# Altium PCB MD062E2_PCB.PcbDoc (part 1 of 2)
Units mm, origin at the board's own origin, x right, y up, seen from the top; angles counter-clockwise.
Board outline 85.34 x 64.01 mm, 4 copper layers (Top Layer, Signal Layer 1, Signal Layer 2, Bottom Layer), stack 1.565 mm thick; 172 components, 94 nets, 455 pads, 231 vias.
Unrouted connection lines stored in the file: 2.
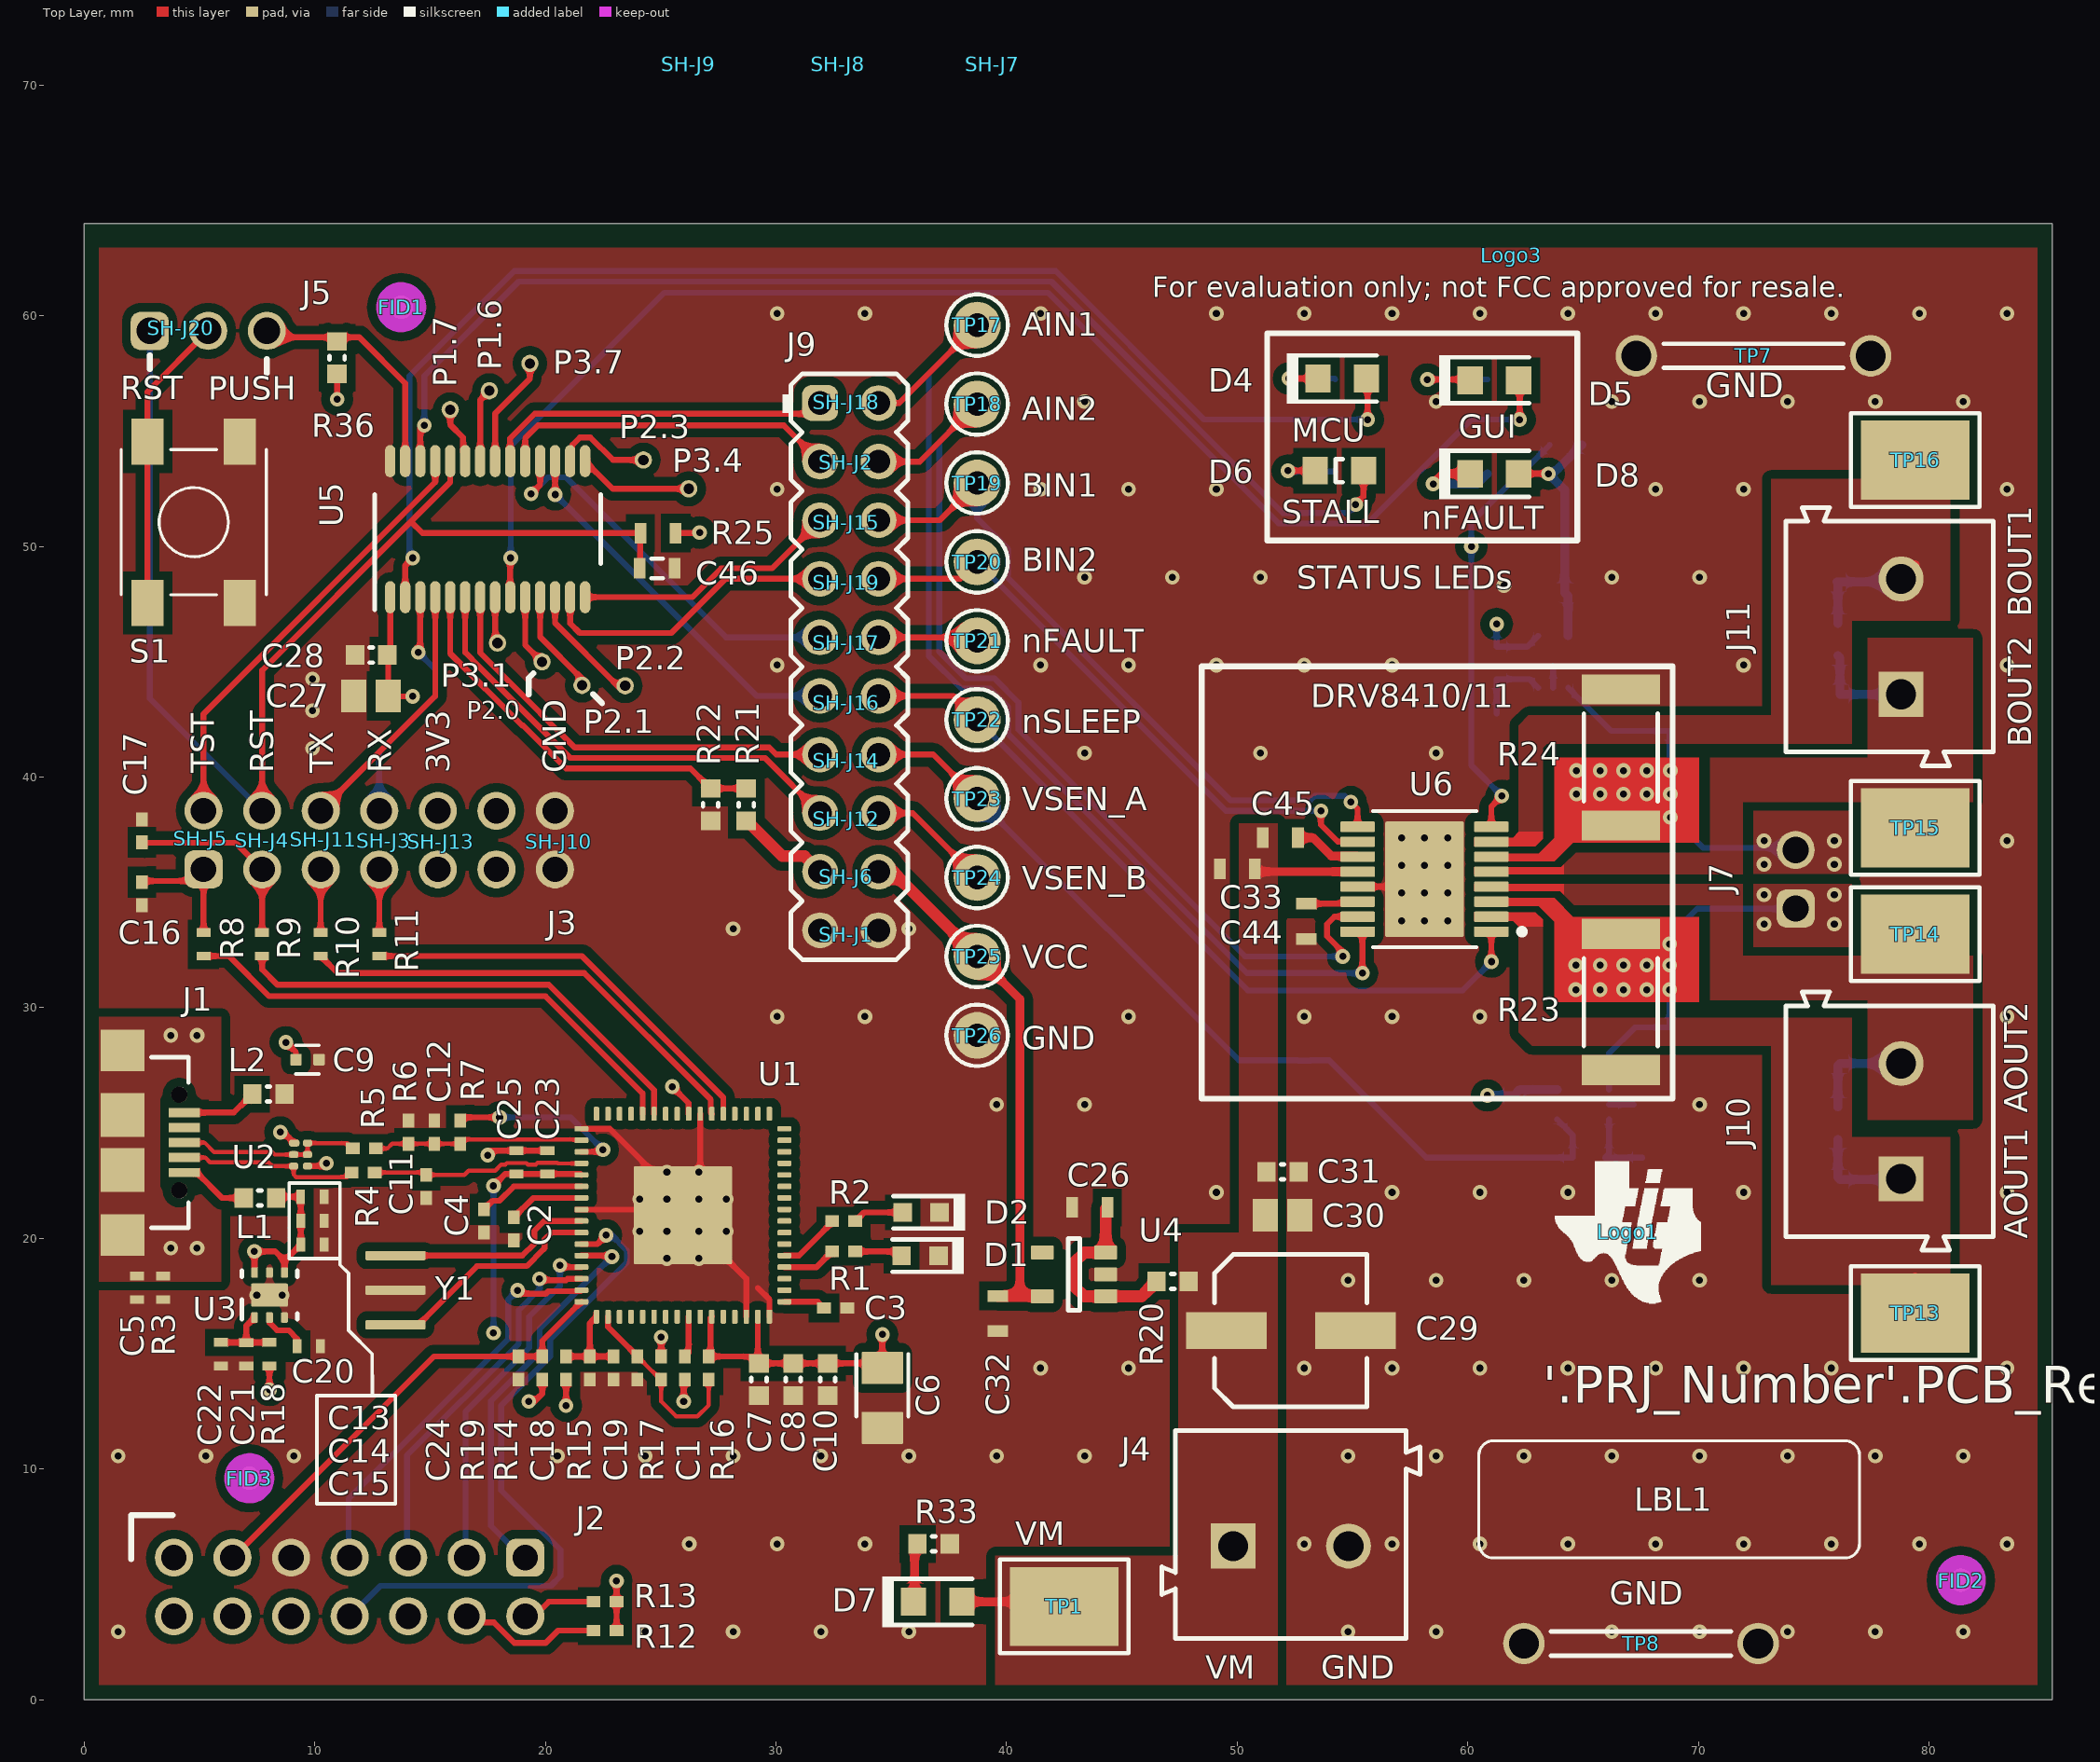
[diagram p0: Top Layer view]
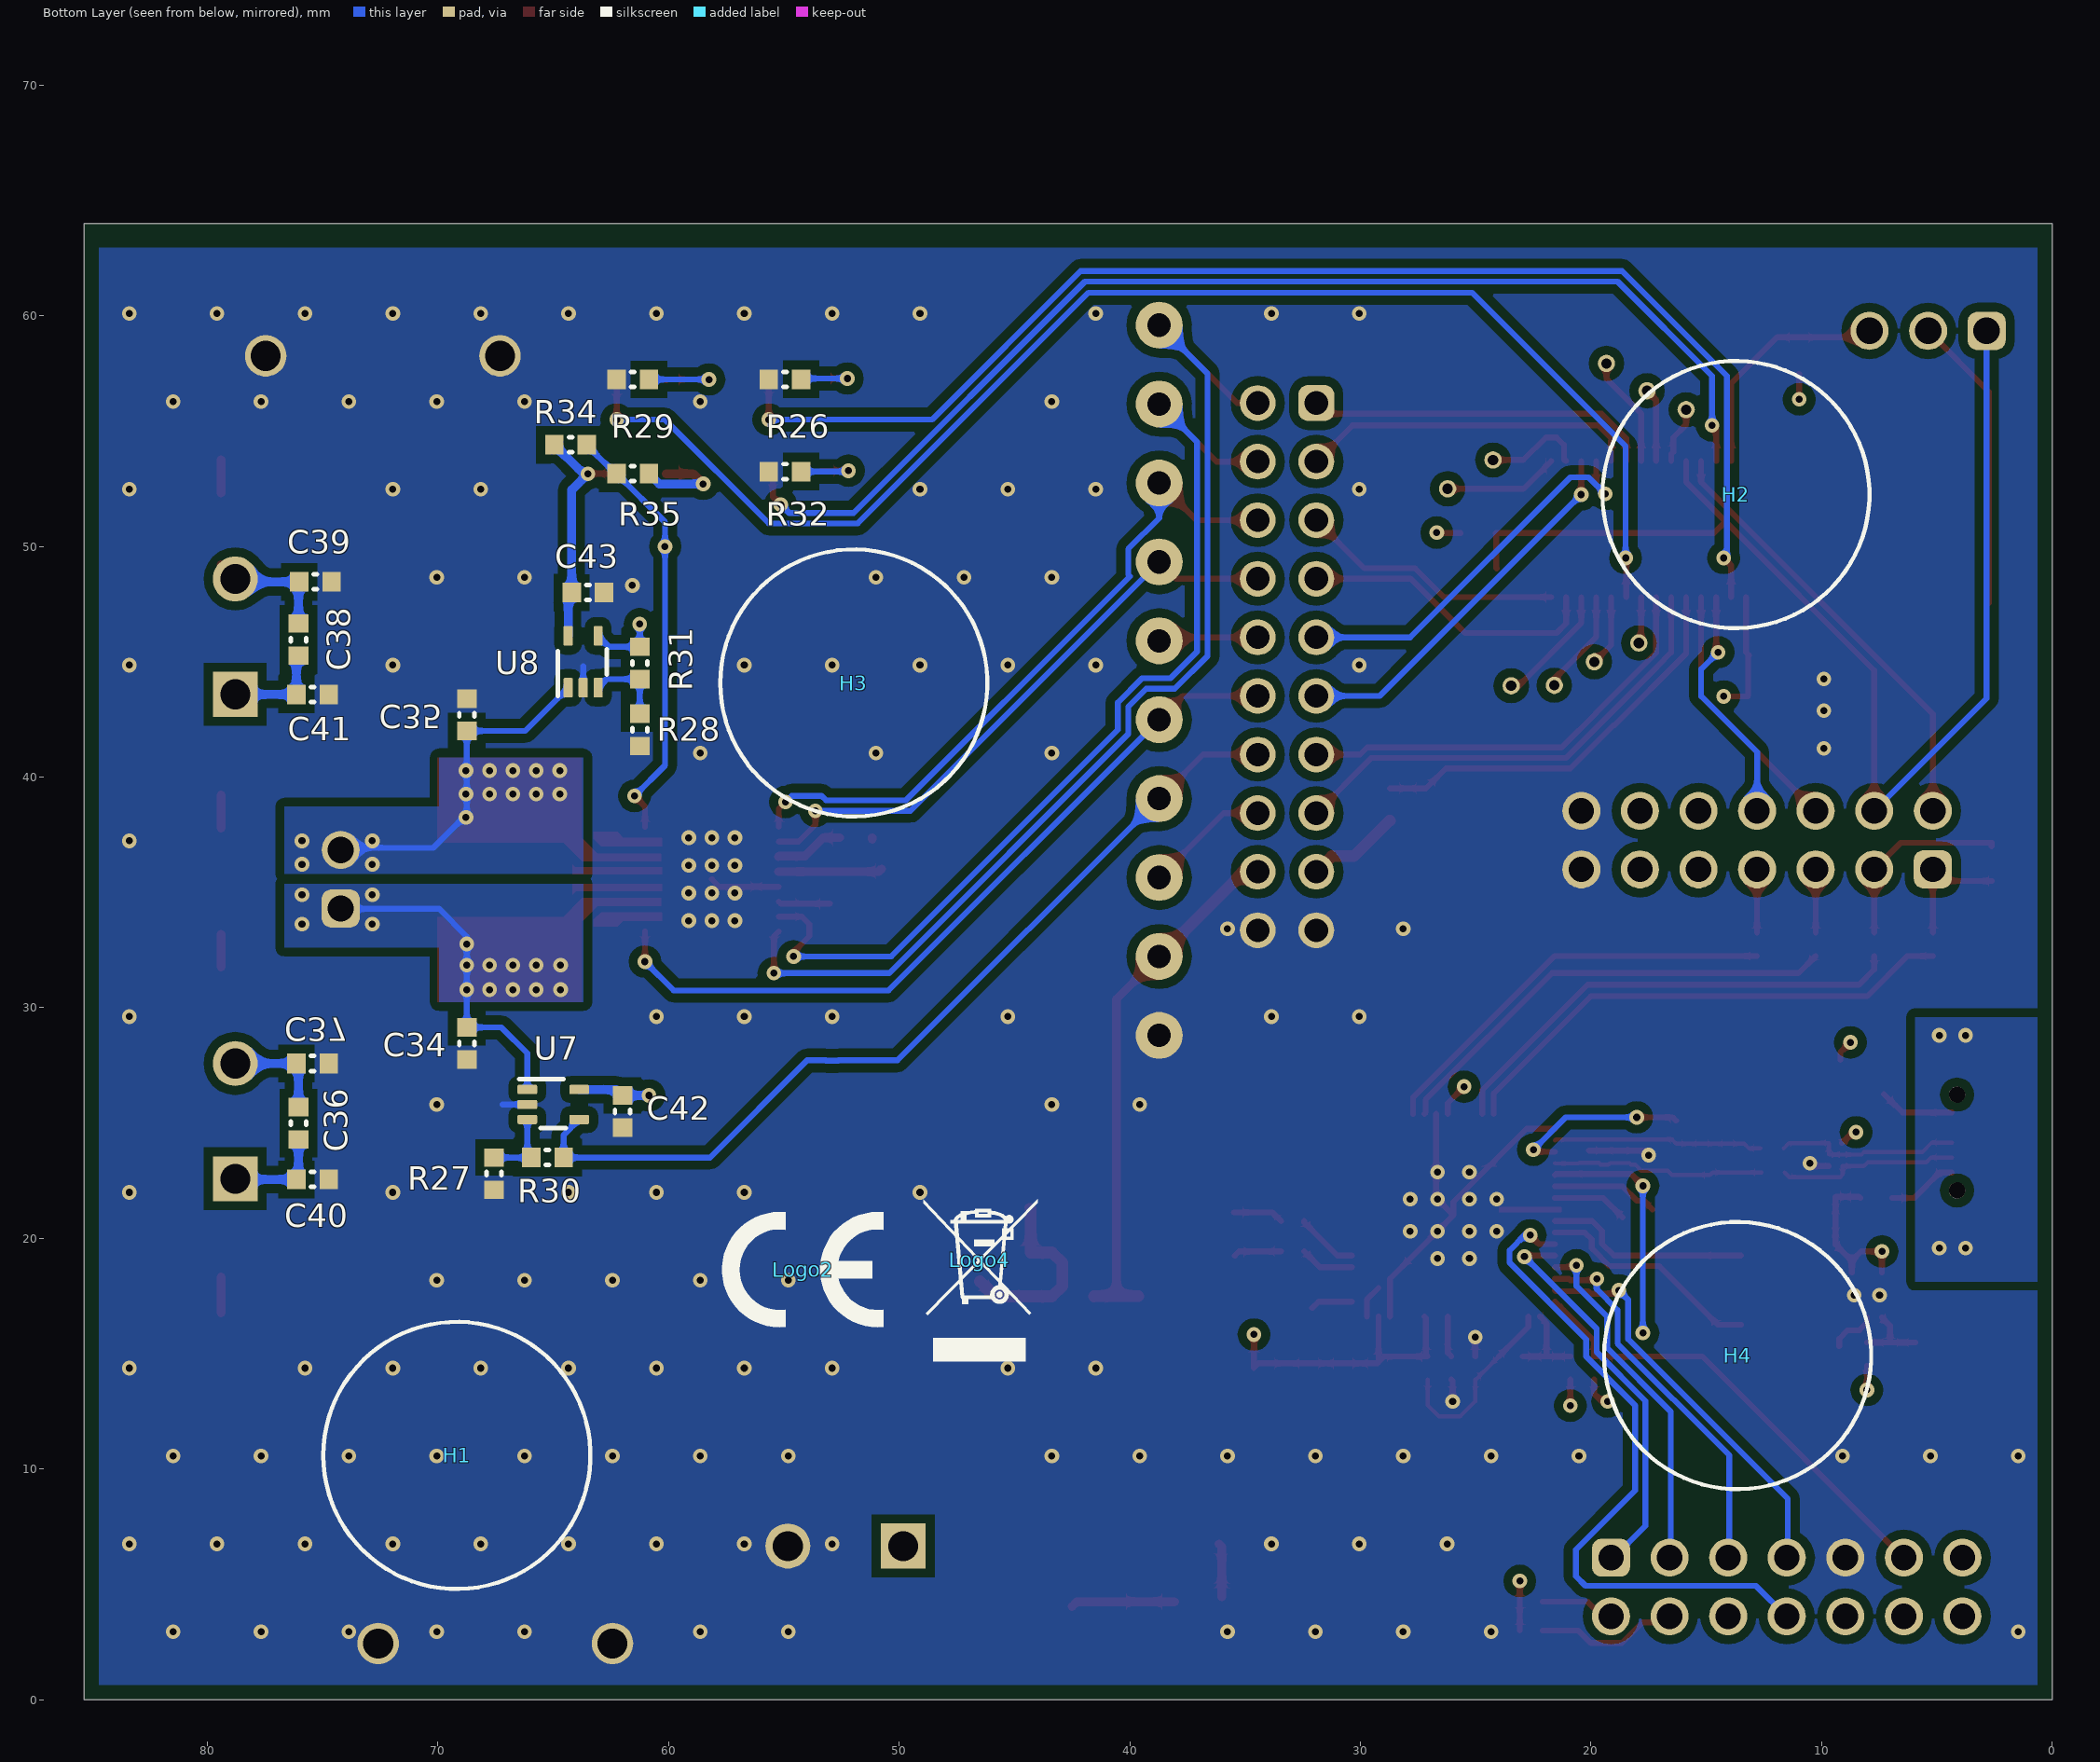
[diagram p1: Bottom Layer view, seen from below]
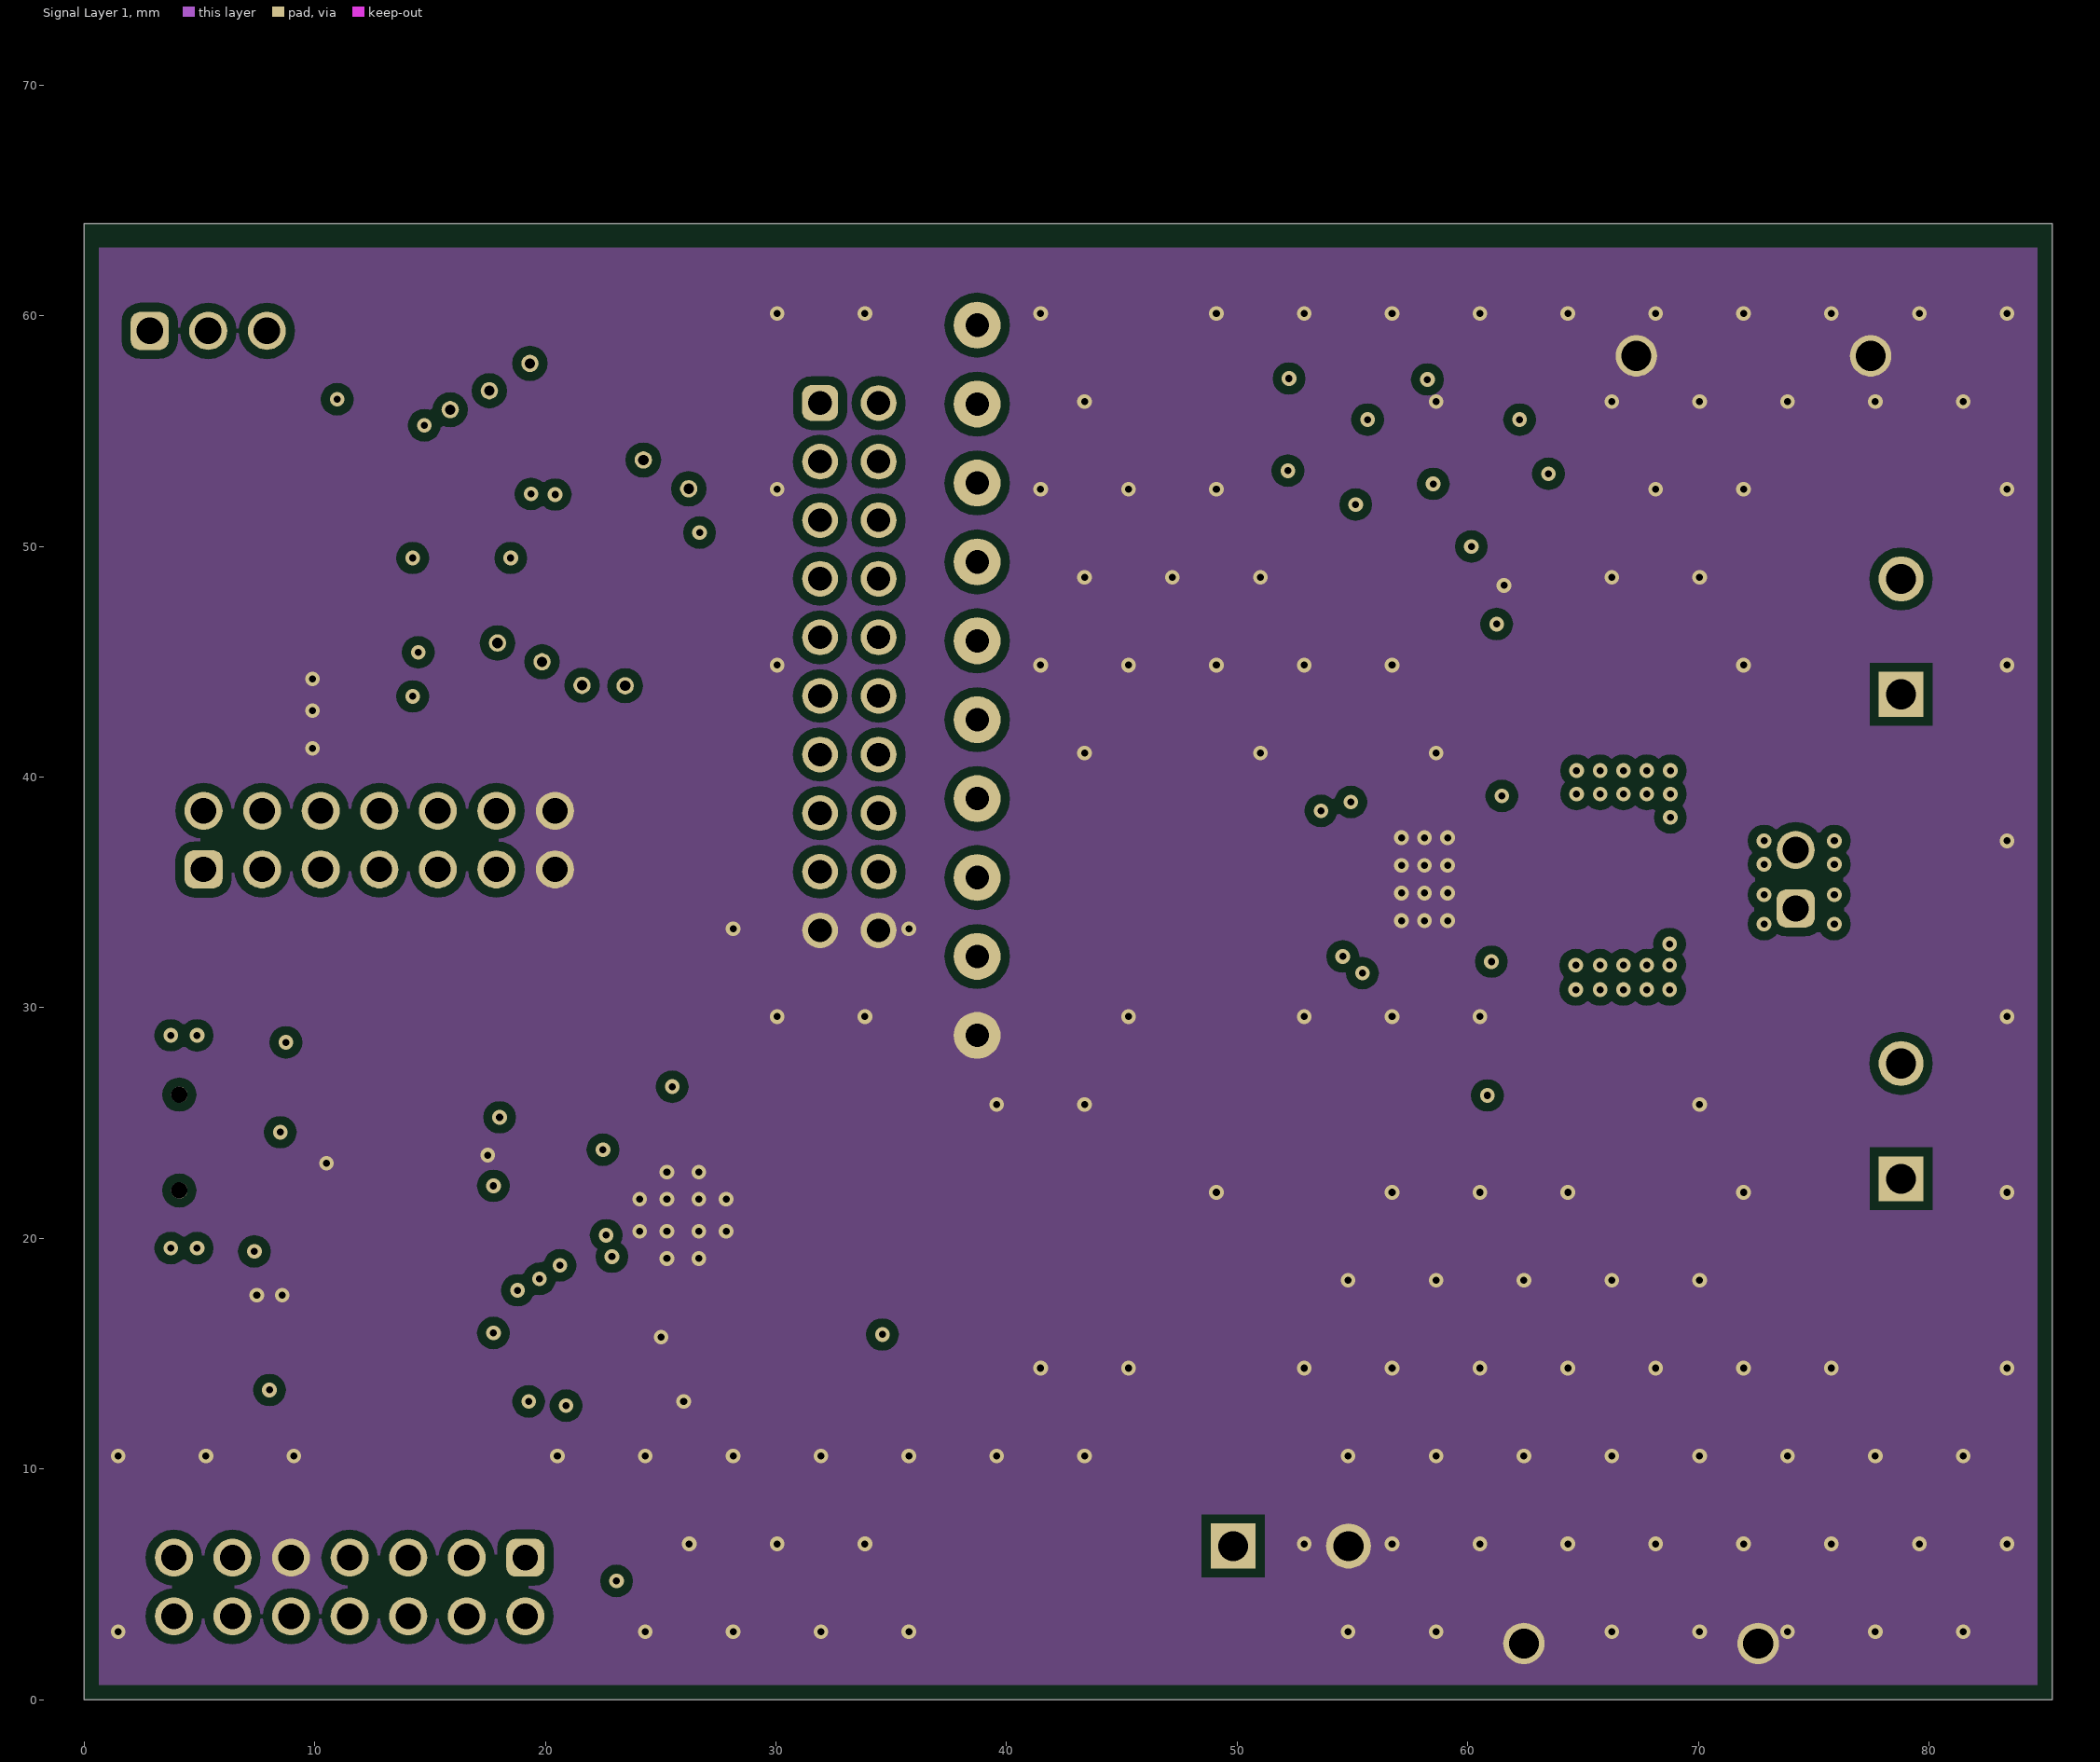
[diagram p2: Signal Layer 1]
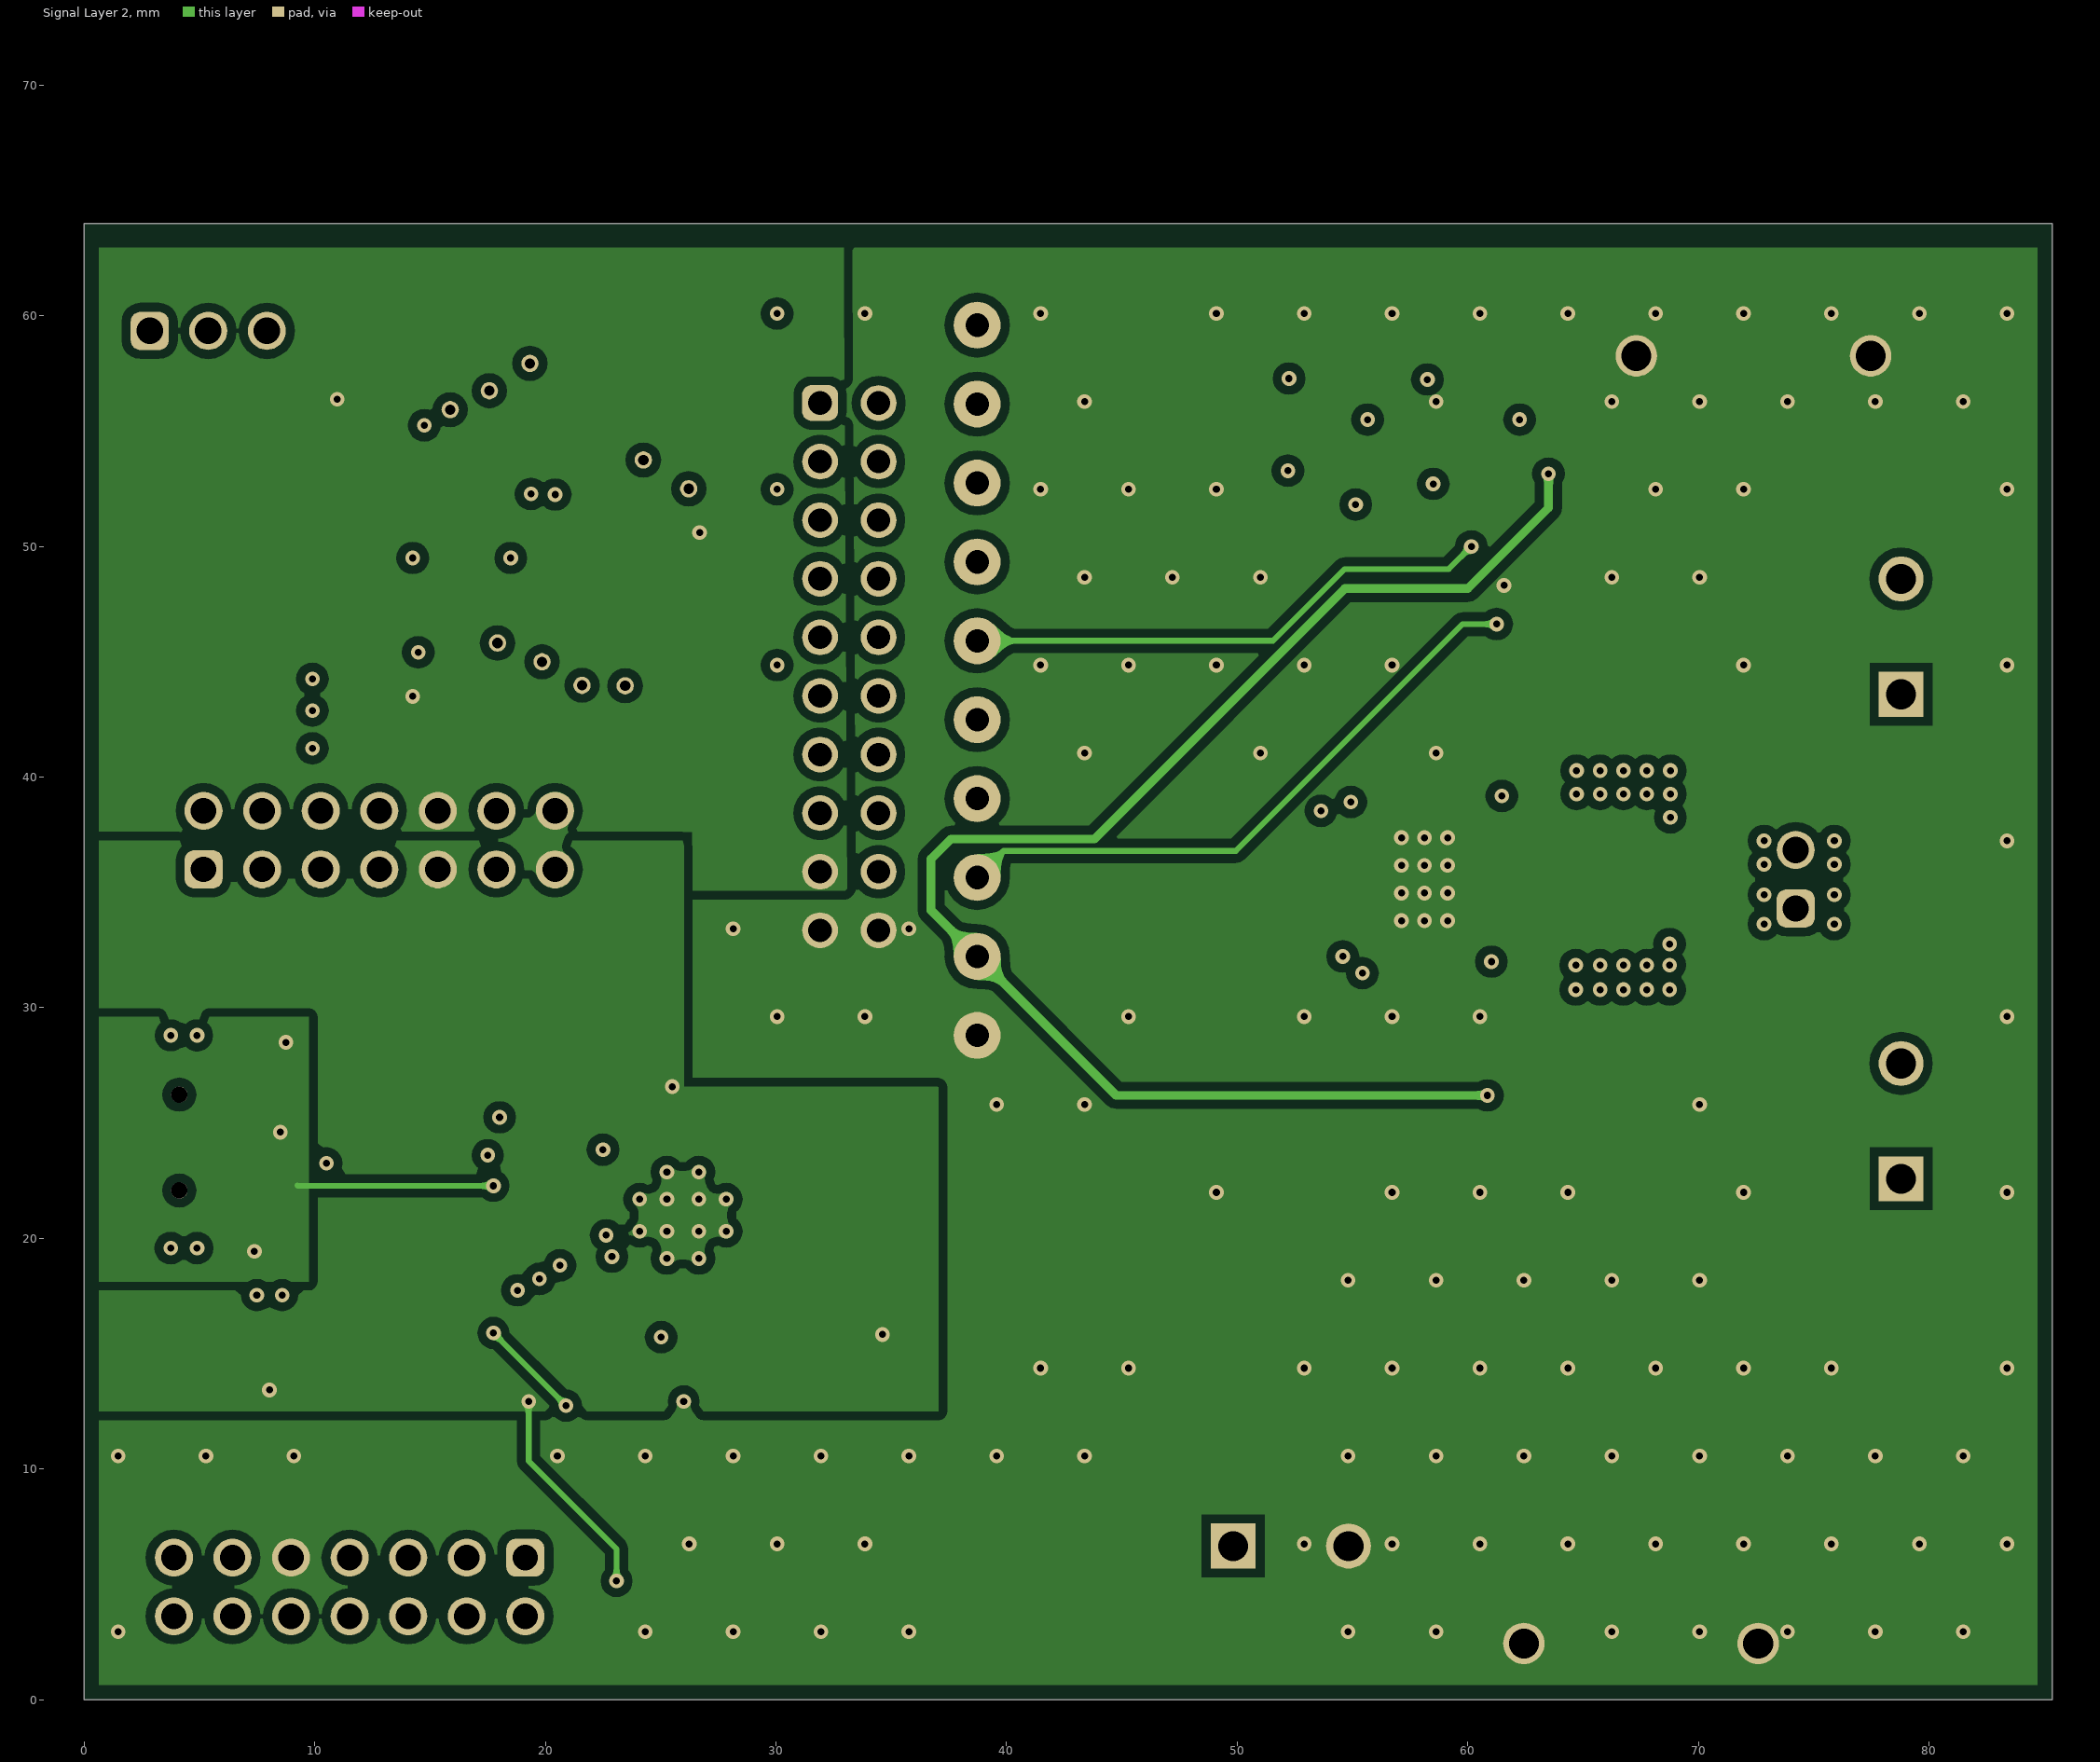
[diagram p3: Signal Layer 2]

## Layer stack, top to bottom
Top Solder: solder mask 0.0102, Solder Resist, Dk 3.5
Top Layer: signal copper 0.0711
Dielectric 1: prepreg 0.2032, FR-4, Dk 4.2
Signal Layer 1: signal copper 0.0356
Dielectric 2: core 0.9449, FR-4, Dk 4.2
Signal Layer 2: signal copper 0.0356
Dielectric 3: prepreg 0.2032, FR-4, Dk 4.2
Bottom Layer: signal copper 0.0711
Bottom Solder: solder mask 0.0102, Solder Resist, Dk 3.5

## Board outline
0,0 85.344,0 85.344,64.008 0,64.008

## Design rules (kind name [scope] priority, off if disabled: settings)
AcuteAngle [All] p1: minimum=4.50000000000000E+0001 checktracksonly=FALSE
AssemblyTestPointUsage [All] p1: valid=2
BoardOutlineClearance BoardOutlineClearance_MountingHoles [OnCopper and InComponentClass('Mounting Holes')] p1: gap=1 ignorepadtopadclearanceinfootprint=FALSE
BoardOutlineClearance BoardOutlineClearance_Poly [OnCopper and IsPoly] p2: gap=0.635 ignorepadtopadclearanceinfootprint=FALSE
BoardOutlineClearance [OnCopper and Not InComponentClass('Logo') and not InComponentClass('FiducialMark') and not InRegion(1000,500,4000,800) and not InPoly] p3: gap=1.905 ignorepadtopadclearanceinfootprint=FALSE
Clearance Clearance_Keepouts [((IsTrack Or IsArc) And Not InPoly) And IsFree and IsKeepOut vs ((IsTrack Or IsArc) And Not InPoly) And IsFree and IsKeepOut] p1: gap=0 ignorepadtopadclearanceinfootprint=FALSE
Clearance Clearance_Poly [InPolygon] p2: gap=0.381 ignorepadtopadclearanceinfootprint=TRUE
Clearance Clearance_FiducialMark [IsKeepOut and InComponentClass('FiducialMark') vs IsPad and InComponentClass('FiducialMark')] p3: gap=0 ignorepadtopadclearanceinfootprint=FALSE
Clearance [All] p4: gap=0.2 ignorepadtopadclearanceinfootprint=TRUE
ComponentClearance ComponentClearance_MountingHoles_FiducialMarks [InComponentClass('Mounting Holes') vs InComponentClass('FiducialMark')] p1: gap=1.27 collisioncheckmode=3 verticalgap=0.254 showdistances=FALSE
ComponentClearance ComponentClearance_Shunt [InComponentClass('Header') vs InComponentClass('Shunt')] p2: gap=0 collisioncheckmode=3 verticalgap=0 showdistances=FALSE
ComponentClearance ComponentClearance_Logo [InComponentClass('Logo')] p3: gap=1.27 collisioncheckmode=3 verticalgap=0.254 showdistances=FALSE
ComponentClearance ComponentClearance_ScrewToNut [(HasFootprint('NY PMS 440 0025 PH')) vs (HasFootprint('Keystone_1902C'))] p4: gap=0.127 collisioncheckmode=3 verticalgap=0.254 showdistances=FALSE
ComponentClearance ComponentClearance_MountingHoles [InComponentClass('Mounting Holes')] p5: gap=6.35 collisioncheckmode=3 verticalgap=2540 showdistances=FALSE
ComponentClearance ComponentClearance_SmallPassives [HasFootprint('0201*') or HasFootprint('0402*') or HasFootprint('0508') or HasFootprint('0603*') or HasFootprint('0612') or HasFootprint('0805*') or HasFootprint('0815*') or HasFootprint('0830*') or HasFootprint('1206*') or HasFootprint('1210*') or HasFootprint('1808*') or HasFootprint('1812*') or HasFootprint('1825*') or HasFootprint('2010*') or HasFootprint('2220*') or HasFootprint('2225*') or HasFootprint('2512*') or HasFootprint('2728*') or HasFootprint('3518*') vs HasFootprint('0201*') or HasFootprint('0402*') or HasFootprint('0508') or HasFootprint('0603*') or HasFootprint('0612') or HasFootprint('0805*') or HasFootprint('0815*') or HasFootprint('0830*') or HasFootprint('1206*') or HasFootprint('1210*') or HasFootprint('1808*') or HasFootprint('1812*') or HasFootprint('1825*') or HasFootprint('2010*') or HasFootprint('2220*') or HasFootprint('2225*') or HasFootprint('2512*') or HasFootprint('2728*') or HasFootprint('3518*')] p6: gap=0.38 collisioncheckmode=3 verticalgap=0.254 showdistances=FALSE
ComponentClearance ComponentClearance_THtoSMT [IsThruComponent vs IsSMTComponent] p7: gap=1.016 collisioncheckmode=3 verticalgap=0.762 showdistances=FALSE
ComponentClearance ComponentClearance_THtoTH [IsThruComponent vs IsThruComponent] p8: gap=0.762 collisioncheckmode=3 verticalgap=0.762 showdistances=FALSE
ComponentClearance [All] p9: gap=0.762 collisioncheckmode=3 verticalgap=0.254 showdistances=FALSE
DiffPairsRouting [All] p1: maxlimit=2.54 minlimit=0.254 mostfreqgap=0.254 toplayer_minwidth=0.178 toplayer_maxwidth=0.381 toplayer_prefwidth=0.381 midlayer1_minwidth=0.178 midlayer1_maxwidth=0.381 midlayer1_prefwidth=0.381 midlayer2_minwidth=0.178 midlayer2_maxwidth=0.381 midlayer2_prefwidth=0.381 bottomlayer_minwidth=0.178 bottomlayer_maxwidth=0.381 bottomlayer_prefwidth=0.381 maxuncoupledlength=25.4
FabricationTestPointUsage TestPointUsage [All] p1: valid=2 allowmultiple=FALSE
FabricationTestpoint Testpoint [All] p1: side=3 testpointundercomponent=TRUE minsize=1.016 maxsize=2.54 preferedsize=1.524 minholesize=0 maxholesize=1.016 preferedholesize=0.813 testpointgrid=0.025 allowsidetop=TRUE allowsidebottom=TRUE usegrid=TRUE gridtolerance=0
FanoutControl Fanout_LCC [IsLCC] p1: bgadir=Out bgaviamode=Centered fanoutstyle=Auto fanoutdirection=Alternating viagrid=0.025 // Fanout_LCC (Default Rule)
FanoutControl Fanout_BGA [IsBGA] p2: bgadir=Out bgaviamode=Centered fanoutstyle=Auto fanoutdirection=Alternating viagrid=0.025 // Fanout_BGA (Default Rule)
FanoutControl Fanout_Default [All] p4: bgadir=Out bgaviamode=Centered fanoutstyle=Auto fanoutdirection=Alternating viagrid=0.025 // Fanout_Default (Default Rule)
FanoutControl Fanout_Small [(CompPinCount < 5)] p5: bgadir=Out bgaviamode=Centered fanoutstyle=Auto fanoutdirection=OutThenIn viagrid=0.025 // Fanout_Small (Default Rule)
HoleSize [All] p1: absolutevalues=TRUE maxlimit=6.375 minlimit=0.2 maxpercent=80.000 minpercent=20.000
MinimumAnnularRing MinimumAnnularRing_ThermalPadVias [IsVia and InAnyComponent] p1: minimumring=0.15
MinimumAnnularRing [All] p2: minimumring=0.2
MinimumSolderMaskSliver MinimumSolderMaskSliver_Logo [InComponentClass('Logo') vs InComponentClass('Logo')] p1: minsoldermaskwidth=0.018
MinimumSolderMaskSliver [All] p2: minsoldermaskwidth=0.1
PlaneClearance [All] p1: clearance=0.381
PlaneConnect [All] p1: planeconnectstyle=Direct reliefexpansion=0.254 reliefentries=4 reliefconductorwidth=0.254 reliefairgap=0.254
PolygonConnect [All] p1: connectstyle=Direct reliefconductorwidth=0.254 reliefentries=4 polygonreliefangle="90 Angle" airgapwidth=0.254
RoutingVias ThermalPadVias [IsVia and InAnyComponent] p1: holewidth=0.305 width=0.66 viastyle="Through Hole" minholewidth=0.152 minwidth=0.5 maxholewidth=0.305 maxwidth=0.66
RoutingVias [All] p2: holewidth=0.406 width=0.864 viastyle="Through Hole" minholewidth=0.2 minwidth=0.66 maxholewidth=1.016 maxwidth=1.651
SilkToBoardRegionClearance [Not ((IsComment or IsDesignator) And (Hide <> 'False')) and not InRegion(1000,500,4000,800)] p1:
SilkToSilkClearance SilkToSilkClearance_Pb-FreeLogo [(HasFootprint('Pb-Free_Overlay_Medium') OR HasFootprint('Pb-Free_Overlay_Small')) vs (HasFootprint('Pb-Free_Overlay_Medium') OR HasFootprint('Pb-Free_Overlay_Small'))] p1: silktosilkclearance=0
SilkToSilkClearance [All] p2: silktosilkclearance=0.1
SilkToSolderMaskClearance SilkToComponentPadClearance [(IsPad or IsFill or IsRegion) and InAnycomponent] p1: minsilkscreentomaskgap=0.127 clearancetoexposedcopper=TRUE
SilkToSolderMaskClearance "Silk to Solder Mask Opening" [All] p2: minsilkscreentomaskgap=0.1 clearancetoexposedcopper=FALSE
SolderMaskExpansion [All] p1: expansion=0.05 istentingtop=FALSE
UnRoutedNet [All] p1: checkbadconnections=TRUE
Width [All] p1: maxlimit=2.54 minlimit=0.152 preferedwidth=0.254 checkconnectedcopper=TRUE
13 further rules are at their usual default settings.

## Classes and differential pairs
net class Power-Net: EZFET_VBUS EZFET_VCC GND VCC
component class Shunt: SH-J1 SH-J2 SH-J3 SH-J4 SH-J5 SH-J6 SH-J7 SH-J8 SH-J9 SH-J10 SH-J11 SH-J12 SH-J13 SH-J14 SH-J15 SH-J16 SH-J17 SH-J18 SH-J19 SH-J20
component class MD062E1_Sch: C26 C27 C28 C29 C30 C31 C32 C33 C34 C35 C36 C37 C38 C39 C40 C41 C42 C43 C44 C45 C46 D4 D5 D6 D7 D8 J4 J5 J7 J9 J10 J11 P1.6 P1.7 P2.0 P2.1 P2.2 P2.3 P3.1 P3.4 P3.7 R20 R21 R22 R23 R24 R25 R26 R27 R28 R29 R30 R31 R32 R33 R34 R35 R36 S1 SH-J7 SH-J8 SH-J9 SH-J10 SH-J11 SH-J12 SH-J13 SH-J14 SH-J15 SH-J16 SH-J17 SH-J18 SH-J19 SH-J20 TP1 TP7 TP8 TP13 TP14 TP15 TP16 TP17 TP18 TP19 TP20 TP21 TP22 TP23 TP24 TP25 TP26 U4 U5 U6 U7 U8
component class Header: J2 J3 J5 J7 J9
component class ezFET: C1 C2 C3 C4 C5 C6 C7 C8 C9 C10 C11 C12 C13 C14 C15 C16 C17 C18 C19 C20 C21 C22 C23 C24 C25 D1 D2 J1 J2 J3 L1 L2 R1 R2 R3 R4 R5 R6 R7 R8 R9 R10 R11 R12 R13 R14 R15 R16 R17 R18 R19 SH-J1 SH-J2 SH-J3 SH-J4 SH-J5 SH-J6 U1 U2 U3 Y1
component class Logo: Logo1
component class MD062E1_Hardware: FID1 FID2 FID3 H1 H2 H3 H4 LBL1 Logo1 Logo2 Logo3 Logo4 ZZ1 ZZ2 ZZ3 ZZ4
component class FiducialMark: FID1 FID2 FID3
component class AssemblyNote: ZZ1 ZZ2 ZZ3 ZZ4
component class Label: LBL1
differential pair USB_D: +USB_D_P -USB_D_N
differential pair EZFET_D: +EZFET_D_P -EZFET_D_N

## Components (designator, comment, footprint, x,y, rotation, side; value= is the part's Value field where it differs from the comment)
C1 "885012105010" 0402L 26.056,14.385 r270 top value=0.1uF
C2 "885012105011" 0402L 18.637,20.413 r270 top value=0.22uF
C3 "GRM155R61C474KE01" 0402L 32.587,16.985 r0 top value=0.47uF
C4 "885012105011" 0402L 17.337,20.76 r270 top value=0.22uF
C5 "885012105011" 0402S 2.286,17.855 r270 top value=0.22uF
C6 "T520A106M010ATE080" 3216-18 34.613,13.085 r270 top value=10uF
C7 "885012206020" 0603L 29.263,13.885 r270 top value=0.1uF
C8 "885012206020" 0603L 30.75,13.885 r270 top value=0.1uF
C9 "885012205018" FP-885012205018_0402-MFG 9.687,27.75 r180 top value=100nF
C10 "885012206020" 0603L 32.237,13.885 r270 top value=0.1uF
C11 "885012005055" 0402L 14.837,22.255 r270 top value=10pF
C12 "885012005055" 0402L 15.187,24.605 r90 top value=10pF
C13 "885012105012" 0402S 9.895,21.803 r0 top value=1uF
C14 "885012105010" 0402S 9.903,20.763 r0 top value=0.1uF
C15 "885012205031" 0402S 9.903,19.735 r0 top value=0.01uF
C16 "885012005055" 0402L 2.507,34.947 r90 top value=10pF
C17 "885012005055" 0402L 2.507,37.67 r270 top value=10pF
C18 "C1005C0G1H330J050BA" 0402L 21.931,14.385 r270 top value=33pF
C19 "C1005C0G1H330J050BA" 0402L 23.994,14.385 r270 top value=33pF
C20 "885012205031" 0402S 9.745,15.327 r0 top value=0.01uF
C21 "885012105013" 0402S 7.034,14.977 r270 top value=2.2uF
C22 "885012105012" 0402S 5.937,14.985 r270 top value=1uF
C23 "C1005X5R1A475M050BC" 0402S 20.087,23.305 r90 top value=4.7uF
C24 "885012205061" 0402L 18.837,14.385 r270 top value=1000pF
C25 "GRM155R61A104KA01D" 0402S 18.75,23.298 r90 top value=0.1uF
C26 "885012206076" 0603S 43.611,21.345 r180 top value=1uF
C27 "885012207025" 0805L 12.437,43.519 r180 top value=4.7uF
C28 "885012206020" 0603L 12.45,45.289 r180 top value=0.1uF
C29 "865080645012" WCAP-ASLI_630x770 52.326,16.002 r0 top value=47uF
C30 "885012207103" 0805L 51.968,21.005 r0 top value=1uF
C31 "885012206095" 0603L 51.968,22.88 r0 top value=0.1uF
C32 "GRM188R61A475ME15" 0603S 39.623,16.745 r270 top value=4.7uF
C33 "885012206095" 0603S 50.012,36.016 r180 top value=0.1uF
C34 "885012206034" 0603L 68.75,28.45 r270 bottom value=1000pF
C35 "885012206034" 0603L 68.75,42.7 r90 bottom value=1000pF
C36 "885012206083" 0603L 76.048,24.994 r90 bottom value=1000pF
C37 "885012206083" 0603L 75.438,27.584 r180 bottom value=1000pF
C38 "885012206083" 0603L 76.048,45.963 r90 bottom value=1000pF
C39 "885012206083" 0603L 75.314,48.463 r180 bottom value=1000pF
C40 "885012206083" 0603L 75.438,22.555 r180 bottom value=1000pF
C41 "885012206083" 0603L 75.438,43.586 r180 bottom value=1000pF
C42 "885012206020" 0603L 62,25.5 r270 bottom value=0.1uF
C43 "885012206020" 0603L 63.5,48 r180 bottom value=0.1uF
C44 "GRM188R61E106KA73D" 0603S 53,33.75 r270 top value=10uF
C45 "C0603C103K4RACTU" 0603S 51.874,37.374 r180 top value=0.01uF
C46 "GRM1885C1E102JA01D" 0603S 24.85,49.05 r0 top value=1000pF
D1 "150060RS75000" WL-SMCW_RED 36.25,19.25 r180 top value=Red
D2 "CMP-0002894-2" WL-SMCW_GREEN 36.3,21.13 r180 top value=Green
D4 "150080VS75000" WL-SMCW_Green_0805 54.554,57.281 r0 top value="Bright Green"
D5 "150080VS75000" WL-SMCW_Green_0805 61.15,57.201 r0 top value="Bright Green"
D6 "Yellow" 0805_A 54.429,53.284 r0 top
D7 "150080VS75000" WL-SMCW_Green_0805 37.012,4.25 r0 top value="Bright Green"
D8 "150080SS75000" WL-SMCW_RED_0805 61.15,53.154 r0 top value=Red
FID1 "Fiducial" Fiducial10-20 13.752,60.371 r0 top
FID2 "Fiducial" Fiducial10-20 81.382,5.182 r0 top
FID3 "Fiducial" Fiducial10-20 7.163,9.601 r0 top
H1 "SJ-5303 (CLEAR)" Bumpon_SJ5003Transparent 69.181,10.592 r180 bottom
H2 "SJ-5303 (CLEAR)" Bumpon_SJ5003Transparent 13.716,52.25 r180 bottom
H3 "SJ-5303 (CLEAR)" Bumpon_SJ5003Transparent 51.968,44.081 r180 bottom
H4 "SJ-5303 (CLEAR)" Bumpon_SJ5003Transparent 13.641,14.921 r180 bottom
J1 "629105136821" 629105136821 1.676,24.156 r90 top
J2 "61301421121" Wurth_61301421121 11.513,4.889 r270 top
J3 "61301421121" Wurth_61301421121 12.798,37.27 r90 top
J4 "691101710002" 691101710002 52.326,7.163 r0 top
J5 "61300311121" WURTH_61300311121 5.385,59.345 r0 top
J7 "61300211121" WURTH_61300211121 74.219,35.574 r90 top
J9 "PEC10DAAN" SULLINS_PEC10DAAN 33.182,44.789 r0 top
J10 "691101710002" 691101710002 78.291,25.085 r90 top
J11 "691101710002" 691101710002 78.291,46.092 r90 top
L1 "742792621" 0603L 7.628,21.755 r0 top value="140 ohm"
L2 "742792621" 0603L 7.992,26.255 r0 top value="140 ohm"
LBL1 "THT-14-423-10" Label_650x200 68.732,8.687 r0 top
Logo1 "Texas Instruments" TI_Symbol_Overlay_Medium 66.934,20.269 r0 top
Logo2 "CE Mark" CE_Mark_5mm 54.177,18.646 r180 bottom
Logo3 "FCC disclaimer" FCC_disclaimer 61.874,62.636 r0 top
Logo4 "WEEE logo" WEEE_Minimum 46.515,19.049 r180 bottom
P1.6 "TP_H0.45P0.75" TP_H045P075 17.572,56.75 r90 top
P1.7 "TP_H0.45P0.75" TP_H045P075 15.875,55.929 r90 top
P2.0 "TP_H0.45P0.75" TP_H045P075 19.857,45 r90 top
P2.1 "TP_H0.45P0.75" TP_H045P075 21.592,43.981 r90 top
P2.2 "TP_H0.45P0.75" TP_H045P075 23.461,43.958 r90 top
P2.3 "TP_H0.45P0.75" TP_H045P075 24.25,53.75 r90 top
P3.1 "TP_H0.45P0.75" TP_H045P075 17.925,45.814 r90 top
P3.4 "TP_H0.45P0.75" TP_H045P075 26.217,52.5 r90 top
P3.7 "TP_H0.45P0.75" TP_H045P075 19.332,57.935 r90 top
R1 "CRCW0402470RJNED" 0402L 32.937,19.435 r180 top value=470
R2 "CRCW0402390RJNED" 0402L 32.937,20.75 r180 top value=390
R3 "CRCW040233K0JNED" 0402S 3.432,17.855 r90 top value=33k
R4 "CRCW040227R0JNED" 0402L 12.1,22.86 r0 top value=27
R5 "CRCW040227R0JNED" 0402L 12.15,23.9 r0 top value=27
R6 "CRCW04021M00JNED" 0402L 14.062,24.605 r270 top value=1.0Meg
R7 "CRCW04021K40FKED" 0402L 16.312,24.605 r90 top value=1.40k
R8 "CRCW040210R0FKED" 0402S 5.178,32.75 r90 top value=10.0
R9 "CRCW040210R0FKED" 0402S 7.718,32.75 r90 top value=10.0
R10 "CRCW040210R0FKED" 0402S 10.258,32.75 r90 top value=10.0
R11 "CRCW040210R0FKED" 0402S 12.803,32.75 r90 top value=10.0
R12 "ERJ-2GE0R00X" 0402L 22.587,3 r180 top value=0
R13 "ERJ-2GE0R00X" 0402L 22.587,4.25 r180 top value=0
R14 "CRCW0402240KFKED" 0402L 20.9,14.385 r270 top value=240k
R15 "CRCW0402150KFKED" 0402L 22.962,14.385 r90 top value=150k
R16 "RC0402FR-07220KL" 0402L 27.087,14.385 r90 top value=220k
R17 "RC0402FR-07220KL" 0402L 25.025,14.385 r270 top value=220k
R18 "CRCW04020000Z0EDHP" 0402S 8.037,14.985 r270 top value=0
R19 "CRCW040247K0JNED" 0402L 19.869,14.385 r270 top value=47k
R20 "ERJ-3GEY0R00V" 0603L 47.2,18.136 r0 top value=0
R21 "CRCW06030000Z0EA" 0603L 28.717,38.809 r270 top value=0
R22 "CRCW06030000Z0EA" 0603L 27.164,38.809 r90 top value=0
R23 "CRM2512-FX-R200ELF" 2512 66.633,30.25 r90 top value=0.2
R24 "CRM2512-FX-R200ELF" 2512 66.633,40.849 r270 top value=0.2
R25 "RC0603JR-0747KL" 0603S 24.89,50.577 r0 top value=47k
R26 "CRCW0603330RJNEA" 0603L 54.954,57.245 r180 bottom value=330
R27 "CRCW06031K02FKEA" 0603L 67.57,22.806 r90 bottom value=1.02k
R28 "CRCW06031K02FKEA" 0603L 61.25,42.05 r90 bottom value=1.02k
R29 "CRCW0603330RJNEA" 0603L 61.55,57.24 r180 bottom value=330
R30 "RT0603DRE079K09L" 0603L 65.25,23.506 r180 bottom value=9.09k
R31 "RT0603DRE079K09L" 0603L 61.25,44.95 r90 bottom value=9.09k
R32 "CRCW0603330RJNEA" 0603L 54.954,53.248 r180 bottom value=330
R33 "CRCW06034K99FKEA" 0603L 36.837,6.755 r180 top value=4.99k
R34 "CRCW060310K0JNEA" 0603L 64.251,54.407 r0 bottom value=10k
R35 "CRCW0603330RJNEA" 0603L 61.55,53.154 r180 bottom value=330
R36 "CRCW060347K0JNEA" 0603L 10.973,58.185 r270 top value=47k
S1 "430481025816" 430481025816 4.75,51.05 r90 top
SH-J1 "60900213421" Wurth_60900213421 33.039,33.19 r180 top
SH-J2 "60900213421" Wurth_60900213421 33.039,53.658 r180 top
SH-J3 "60900213421" Wurth_60900213421 13,37.25 r270 top
SH-J4 "60900213421" Wurth_60900213421 7.712,37.273 r270 top
SH-J5 "60900213421" Wurth_60900213421 5.055,37.34 r270 top
SH-J6 "60900213421" Wurth_60900213421 33.039,35.697 r180 top
SH-J7 "60900213421" Wurth_60900213421 39.384,70.92 r90 top
SH-J8 "60900213421" Wurth_60900213421 32.704,70.92 r90 top
SH-J9 "60900213421" Wurth_60900213421 26.204,70.92 r90 top
SH-J10 "60900213421" Wurth_60900213421 20.574,37.213 r270 top
SH-J11 "60900213421" Wurth_60900213421 10.375,37.313 r270 top
SH-J12 "60900213421" Wurth_60900213421 33.039,38.204 r180 top
SH-J13 "60900213421" Wurth_60900213421 15.468,37.199 r270 top
SH-J14 "60900213421" Wurth_60900213421 33.039,40.71 r180 top
SH-J15 "60900213421" Wurth_60900213421 33.039,51.048 r180 top
SH-J16 "60900213421" Wurth_60900213421 33.039,43.217 r180 top
SH-J17 "60900213421" Wurth_60900213421 33.039,45.827 r180 top
SH-J18 "60900213421" Wurth_60900213421 33.039,56.268 r180 top
SH-J19 "60900213421" Wurth_60900213421 33.039,48.437 r180 top
SH-J20 "60900213421" Wurth_60900213421 4.185,59.469 r180 top
TP1 "5016" Testpoint_Keystone_Compact 42.5,4.043 r0 top
TP7 "CMP-0075110-1" Harwin_D3082-05 72.39,58.262 r180 top
TP8 "CMP-0075110-1" Harwin_D3082-05 67.513,2.438 r180 top
TP13 "5016" Testpoint_Keystone_Compact 79.4,16.764 r180 top
TP14 "5016" Testpoint_Keystone_Compact 79.4,33.19 r0 top
TP15 "5016" Testpoint_Keystone_Compact 79.4,37.795 r180 top
TP16 "5016" Testpoint_Keystone_Compact 79.4,53.75 r0 top
TP17 "5002" Keystone5002 38.725,59.594 r0 top
TP18 "5002" Keystone5002 38.725,56.173 r0 top
TP19 "5002" Keystone5002 38.725,52.752 r0 top
TP20 "5002" Keystone5002 38.725,49.331 r0 top
TP21 "5002" Keystone5002 38.725,45.909 r0 top
TP22 "5002" Keystone5002 38.725,42.488 r0 top
TP23 "5002" Keystone5002 38.725,39.067 r0 top
TP24 "5002" Keystone5002 38.725,35.646 r0 top
TP25 "5002" Keystone5002 38.725,32.225 r0 top
TP26 "5002" Keystone5002 38.725,28.804 r0 top
U1 "CMP-0039269-4" RGC0064B 25.967,21.005 r90 top
U2 "TPD2E001DRYR" DRY0006A 9.387,23.635 r0 top
U3 "TPS73533DRVR" DRV0006A 8.037,17.545 r90 top
U4 "TPS70933DBVR" DBV0005A_N 42.922,18.44 r180 top
U5 "MSP430G2553IPW28R" PW0028A_N 17.5,50.75 r90 top
U6 "DRV8410PWPR" PWP0016C-MFG 58.124,35.574 r180 top
U7 "TLV6001IDCKR" DCK0005A_N 65,25.806 r180 bottom
U8 "TLV6001IDCKR" DCK0005A_N 63.703,45 r90 bottom
Y1 "CSTNR4M00GH5L000R0" MuRata_CSTNR 13.5,17.755 r270 top
ZZ1 "This Assembly Note is for PCB labels only" AssemblyNoteLabel 4.699,100.025 r0 top
ZZ2 "These assemblies are ESD sensitive, ESD precautions shall be observed." AssemblyNote 4.699,97.259 r0 top
ZZ3 "These assemblies must be clean and free from flux and all contaminants. Use of no clean flux is not acceptable." AssemblyNote 4.699,95.01 r0 top
ZZ4 "These assemblies must comply with workmanship standards IPC-A-610 Class 2, unless otherwise specified." AssemblyNote 4.699,92.761 r0 top

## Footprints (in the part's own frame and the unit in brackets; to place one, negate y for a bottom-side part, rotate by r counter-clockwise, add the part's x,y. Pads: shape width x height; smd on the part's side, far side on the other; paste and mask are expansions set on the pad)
0402L [mm] "0402 from SM-752 data"
  rect 0.6x0.5 smd: 1(-0.5,0) 2(0.5,0)
  body extent -0.55,-0.3 0.55,0.3, height 0.6
0402S [mil] "Based on C0402S footprint from PADS legacy"
  rect 15x24 smd: 1(-20,0) 2(20,0)
  body extent -22,-12 22,12, height 24
0603L [mm] "0603 from SM-752 data"
  rect 0.8x0.85 smd: 1(-0.7,0) 2(0.7,0)
  silkscreen extent -0.07,-0.33 0.07,0.33, body extent -0.87,-0.47 0.87,0.47, height 1
0603S [mil]
  rect 20x35 smd: 1(-30,0) 2(30,0)
  body extent -34,-19 34,19, height 39
0805_A [mm] "Chip LED, 2-Leads, Body 2.0x1.3mm, IPC Medium Density"
  rect 1.1x1.2 smd: 1(-1.05,0) 2(1.05,0)
  silkscreen extent -0.15,-0.5 0.15,0.5, body extent -1,-0.62 1,0.63, height 0.68
0805L [mm] "0805 from SM-752 data"
  rect 1.1x1.4 smd: 1(-0.75,0) 2(0.75,0)
  body extent -1.1,-0.72 1.1,0.72, height 1.45
2512 [mm] "Chip Resistor, Body 6.3x3.2mm, IPC Medium Density"
  rect 1.3x3.4 smd: 1(-2.95,0) 2(2.95,0)
  silkscreen extent -1.9,-1.6 1.9,1.6, body extent -3.22,-1.67 3.22,1.67, height 0.71
3216-18 [mm] "Based on AVX recommendation in http://www.avx.com/download/software/literature/AVX-Footprint-Library.pdf"
  rrect7% 1.4x1.8 smd: 1(-1.3,0) 2(1.3,0)
  silkscreen extent -1.9,-1.12 0.8,1.12, body extent -1.7,-0.9 1.7,0.9, height 1.82
430481025816 [mm] "6*6mm vertical type,SMD, height 2.5mm, black actuator, 160gf, T&R"
  rect 2x1.4 smd: 1(-3.5,2) 2(3.5,2) 3(-3.5,-2) 4(3.5,-2)
  silkscreen extent -3.15,-3.15 3.15,3.15, body extent -4,-3.1 4,3.1, height 2.49
629105136821 [mm] "Micro USB 2.0 SMT Type B Horizontal 5 Contacts"
  rect 0.4x1.35 smd: 1(-1.3,-2.675) 2(-0.65,-2.675) 3(0,-2.675) 4(0.65,-2.675) 5(1.3,-2.675)
  round 0.7 hole 0.7 unplated: MH1(-2.075,-2.45) MH2(2.075,-2.45)
  rect 1.8x1.9 smd: Shell(-4,0) Shell(4,0)
  rect 1.9x1.9 smd: Shell(-1.2,0) Shell(1.2,0)
  silkscreen extent -3.7,-2.85 3.7,-1.25, body extent -4,-3.17 4,2.73, height 2.69
691101710002 [mm] "5,00mm - modular - blue - Horizontal entry with pressure clamp - 12,6mm height - 02p"
  rect 1.95x1.95 hole 1.3: 1(-2.5,-0.5)
  round 1.95 hole 1.3: 2(2.5,-0.5)
  silkscreen extent -5.6,-4.5 5.6,4.5, body extent -5.6,-4.5 5.6,4.5, height 12.65
AssemblyNote [mm] "Assembly Note"
AssemblyNoteLabel [mm] "Assembly Note for PCB Labels"
Bumpon_SJ5003Transparent [mil] "3M Hemispherical Bumpon transparent"
  round 1 on Mech4: 0(0,0)
  silkscreen extent -228,-228 228,228, body extent -219,-219 219,219, height 197
CE_Mark_5mm [mm] "Minimum text height for CE Mark"
  silkscreen extent -3.5,-2.5 3.5,2.5
DBV0005A_N [mm] "SOT23, 5-Leads, Body 2.9x1.6mm, Pitch 0.95mm, Lead Span 2.8mm, IPC Medium Density"
  rrect17% 1x0.6 smd: 1(-1.375,0.95) 2(-1.375,0) 3(-1.375,-0.95) 4(1.375,-0.95) 5(1.375,0.95)
  silkscreen extent -0.25,-1.55 0.25,1.55, body extent -1.42,-1.46 1.42,1.46, height 1.09
DCK0005A_N [mm] "SOT353, 5-Leads, Body 2x1.3mm, Pitch 0.65mm, Lead Span 2.1mm, IPC Medium Density"
  rrect25% 0.85x0.4 smd: 1(-1.125,0.65) 2(-1.125,0) 3(-1.125,-0.65) 4(1.125,-0.65) 5(1.125,0.65)
  silkscreen extent -1.48,-1.02 0.55,1.1, body extent -1.14,-1 1.14,1, height 0.95
DRV0006A [mm] "SON, 6-Leads, Body 2x2mm, Pitch 0.65mm, Thermal Pad 1.6x1mm, TI Recommended"
  rrect33% 0.45x0.3 smd: 1(-0.975,0.65) 2(-0.975,0) 3(-0.975,-0.65) 4(0.975,-0.65) 5(0.975,0) 6(0.975,0.65)
  rrect14% 1x0.7 on Top Paste: 7(0,0.45) 7(0,-0.45)
  rrect10% 1x1.6 smd paste-0.5: 7(0,0)
  silkscreen extent -1.05,-1.2 1.05,1.2, body extent -1.05,-1.05 1.05,1.05, height 0.81
DRY0006A [mm] "USON-6"
  rrect67% 0.45x0.3 smd paste-0.05 mask-0.05: 1(-0.275,0.5)
  rrect67% 0.4x0.3 smd paste-0.05 mask-0.05: 2(-0.3,0) 3(-0.3,-0.5) 4(0.3,-0.5) 5(0.3,0) 6(0.3,0.5)
  body extent -0.5,-0.72 0.5,0.73, height 0.58
FCC_disclaimer [mm]
Fiducial10-20 [mm]
  round 1 smd mask+0.5: 1(0,0)
  Top Layer keep-out circle w1.178: c0,0 r0.5
FP-885012205018_0402-MFG [mm]
  rrect20% 0.5x0.5 smd paste+0 mask+0: 1(-0.5,0) 2(0.5,0)
  silkscreen extent -0.5,-0.63 0.5,0.63, body extent -0.85,-0.38 0.85,0.38, height 0.25
Harwin_D3082-05 [mm] "Shorting Plug, 10.16mm spacing, TH"
  round 1.8 hole 1.3: 1(-5.08,0) 2(5.08,0)
  silkscreen extent -3.9,-0.53 3.9,0.53, body extent -5.6,-0.52 5.61,0.52, height 6.63
Keystone5002 [mil] "For Keystone 500x miniature loop terminals"
  round 80 hole 40: 1(0,0)
  silkscreen extent -52,-52 52,52, body extent -49,-49 49,49, height 182
Label_650x200 [mil] "Thermal Transfer Label"
  round 1 on Mech13: 0(0,0)
  silkscreen extent -325,-100 325,100, body extent -325,-100 325,100, height 1
MuRata_CSTNR [mm] "SMD, 3-Leads, Body 4.5x2mm, Pitch 1.5mm"
  rrect25% 0.4x2.6 smd: 1(-1.5,0) 2(0,0) 3(1.5,0)
  body extent -2.3,-1.05 2.3,1.05, height 1.2
PW0028A_N [mm] "TSOP, 28-Leads, Body 9.7x4.4mm, Pitch 0.65mm, IPC Medium Density"
  oval 1.4x0.45 smd: 1(-2.95,4.225) 2(-2.95,3.575) 3(-2.95,2.925) 4(-2.95,2.275) 5(-2.95,1.625) 6(-2.95,0.975) 7(-2.95,0.325) 8(-2.95,-0.325) 9(-2.95,-0.975) 10(-2.95,-1.625) 11(-2.95,-2.275) 12(-2.95,-2.925) 13(-2.95,-3.575) 14(-2.95,-4.225) 15(2.95,-4.225) 16(2.95,-3.575) 17(2.95,-2.925) 18(2.95,-2.275) 19(2.95,-1.625) 20(2.95,-0.975) 21(2.95,-0.325) 22(2.95,0.325) 23(2.95,0.975) 24(2.95,1.625) 25(2.95,2.275) 26(2.95,2.925) 27(2.95,3.575) 28(2.95,4.225)
  silkscreen extent -3.5,-4.9 1.5,4.9, body extent -3.21,-4.85 3.21,4.85, height 1
PWP0016C-MFG [mm]
  rrect22% 1.5x0.45 smd paste+0 mask+0: 1(-2.9,2.275) 2(-2.9,1.625) 3(-2.9,0.975) 4(-2.9,0.325) 5(-2.9,-0.325) 6(-2.9,-0.975) 7(-2.9,-1.625) 8(-2.9,-2.275) 9(2.9,-2.275) 10(2.9,-1.625) 11(2.9,-0.975) 12(2.9,-0.325) 13(2.9,0.325) 14(2.9,0.975) 15(2.9,1.625) 16(2.9,2.275)
  rrect3% 3.4x5 smd paste-1000 mask-1000: 17(0,0)
  silkscreen extent -4.35,-2.95 2.25,2.95, body extent -3.75,-2.8 3.75,2.8, height 0.25
RGC0064B [mm] "VQFN-64"
  rrect42% 0.6x0.24 smd mask+0.07: 1(-4.4,3.75) 2(-4.4,3.25) 3(-4.4,2.75) 4(-4.4,2.25) 5(-4.4,1.75) 6(-4.4,1.25) 7(-4.4,0.75) 8(-4.4,0.25) 9(-4.4,-0.25) 10(-4.4,-0.75) 11(-4.4,-1.25) 12(-4.4,-1.75) 13(-4.4,-2.25) 14(-4.4,-2.75) 15(-4.4,-3.25) 16(-4.4,-3.75) 33(4.4,-3.75) 34(4.4,-3.25) 35(4.4,-2.75) 36(4.4,-2.25) 37(4.4,-1.75) 38(4.4,-1.25) 39(4.4,-0.75) 40(4.4,-0.25) 41(4.4,0.25) 42(4.4,0.75) 43(4.4,1.25) 44(4.4,1.75) 45(4.4,2.25) 46(4.4,2.75) 47(4.4,3.25) 48(4.4,3.75)
  rrect42% 0.24x0.6 smd mask+0.07: 17(-3.75,-4.4) 18(-3.25,-4.4) 19(-2.75,-4.4) 20(-2.25,-4.4) 21(-1.75,-4.4) 22(-1.25,-4.4) 23(-0.75,-4.4) 24(-0.25,-4.4) 25(0.25,-4.4) 26(0.75,-4.4) 27(1.25,-4.4) 28(1.75,-4.4) 29(2.25,-4.4) 30(2.75,-4.4) 31(3.25,-4.4) 32(3.75,-4.4) 49(3.75,4.4) 50(3.25,4.4) 51(2.75,4.4) 52(2.25,4.4) 53(1.75,4.4) 54(1.25,4.4) 55(0.75,4.4) 56(0.25,4.4) 57(-0.25,4.4) 58(-0.75,4.4) 59(-1.25,4.4) 60(-1.75,4.4) 61(-2.25,4.4) 62(-2.75,4.4) 63(-3.25,4.4) 64(-3.75,4.4)
  rrect2% 4.25x4.25 smd paste-2.112: 65(0,0)
  body extent -4.5,-4.5 4.5,4.5, height 1
SULLINS_PEC10DAAN [mm] "SULLINS"
  rrect50% 1.55x1.55 hole 1.016: 1(-1.27,11.43)
  round 1.55 hole 1.016: 2(1.27,11.43) 3(-1.27,8.89) 4(1.27,8.89) 5(-1.27,6.35) 6(1.27,6.35) 7(-1.27,3.81) 8(1.27,3.81) 9(-1.27,1.27) 10(1.27,1.27) 11(-1.27,-1.27) 12(1.27,-1.27) 13(-1.27,-3.81) 14(1.27,-3.81) 15(-1.27,-6.35) 16(1.27,-6.35) 17(-1.27,-8.89) 18(1.27,-8.89) 19(-1.27,-11.43) 20(1.27,-11.43)
  silkscreen extent -2.9,-12.7 2.54,12.7, body extent -2.54,-12.7 2.54,12.7, height 8.38
Testpoint_Keystone_Compact [mil] "Compact SMT test point"
  rect 185x135 smd: 1(0,0)
  silkscreen extent -110,-80 110,80, body extent -75,-56 75,56, height 91
TI_Symbol_Overlay_Medium [mm]
  silkscreen extent -3.16,-3.09 3.16,3.06
TP_H045P075 [mm] "TP_H0.45P0.75"
  round 0.75 hole 0.45: 1(0,0)
WCAP-ASLI_630x770 [mm] "SMD, 2-Leads, Dia 6.3mm"
  rect 3.5x1.6 smd: 1(-2.8,0) 2(2.8,0)
  silkscreen extent -3.3,-3.3 3.3,3.3, body extent -3.3,-3.3 3.3,3.3, height 7.7
WEEE_Minimum [mm] "WEEElie bin"
  silkscreen extent -2.42,-4.38 2.52,2.65
WL-SMCW_GREEN [mm] "WURTH"
  rect 0.8x0.8 smd: 1(-0.8,0) 2(0.8,0)
  silkscreen extent -1.9,-0.8 1.2,0.8, body extent -0.85,-0.45 0.85,0.45, height 0.8
WL-SMCW_Green_0805 [mm] "SMD, 2-Leads, Body 2x1.25mm"
  rect 1.1x1.2 smd: 1(-1.05,0) 2(1.05,0)
  silkscreen extent -2.4,-1.1 1.5,1.1, body extent -1,-0.62 1,0.63, height 0.7
WL-SMCW_RED [mm] "WURTH"
  rect 0.8x0.8 smd: 1(-0.8,0) 2(0.8,0)
  silkscreen extent -1.9,-0.8 1.2,0.8, body extent -0.85,-0.45 0.85,0.45, height 0.8
WL-SMCW_RED_0805 [mm] "SMD, 2-Leads, Body 1.6x0.8mm"
  rect 1.1x1.2 smd: 1(-1.05,0) 2(1.05,0)
  silkscreen extent -2.4,-1.1 1.5,1.1, body extent -1,-0.62 1,0.63, height 0.7
Wurth_60900213421 [mil] "Shunt, 2.54mm, Black"
  round 1 on Mech3: 0(0,0)
  body extent -98,-48 98,48, height 338
WURTH_61300211121 [mm] "Header, 2.54mm, 2x1, TH"
  rrect50% 1.65x1.65 hole 1.15: 1(-1.27,0)
  round 1.65 hole 1.15: 2(1.27,0)
  body extent -2.54,-1.27 2.54,1.27, height 8.54
WURTH_61300311121 [mm] "Header, 2.54mm, 3x1, TH"
  rrect50% 1.65x1.65 hole 1.15: 1(-2.54,0)
  round 1.65 hole 1.15: 2(0,0) 3(2.54,0)
  body extent -3.81,-1.27 3.81,1.27, height 8.54
Wurth_61301421121 [mm] "Header, 2.54mm, 7x2, TH"
  rrect50% 1.65x1.65 hole 1.1: 1(-1.27,7.62)
  round 1.65 hole 1.1: 2(1.27,7.62) 3(-1.27,5.08) 4(1.27,5.08) 5(-1.27,2.54) 6(1.27,2.54) 7(-1.27,0) 8(1.27,0) 9(-1.27,-2.54) 10(1.27,-2.54) 11(-1.27,-5.08) 12(1.27,-5.08) 13(-1.27,-7.62) 14(1.27,-7.62)
  body extent -2.54,-8.89 2.54,8.89, height 8.55

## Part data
C1 C14: library part CMP-0006221-2, "CAP, CERM, 0.1 uF, 10 V, +/- 20%, X5R, 0402", Cap_Case=0402, Manufacturer="Wurth Elektronik", Supplier Part Number 1=732-7487-1-ND, TempCo=X5R, Tolerance_%=20%, Value1=Unknown, Value2=10V, ValueDisplayed=0.1uF
C2 C4 C5: library part CMP-0078875-1, "CAP, CERM, 0.22 µF, 10 V,+/- 20%, X5R, 0402", Cap_Case=0402, Manufacturer="Wurth Elektronik", Supplier Part Number 1=732-7488-1-ND, TempCo=X5R, Tolerance_%=20%, Value2=10V, ValueDisplayed=0.22µF
C3: library part CMP-0006600-2, "CAP, CERM, 0.47 uF, 16 V, +/- 10%, X5R, 0402", Cap_Case=0402, Manufacturer=MuRata, TempCo=X5R, Tolerance_%=10%, Value1=Unknown, Value2=16V, ValueDisplayed=0.47uF
C6: library part CMP-0084376-1, "CAP, Tantalum Polymer, 10 µF, 10 V,+/- 20%, 0.08 ohm, 3216-18 SMD", Cap_Case=3216-18, Manufacturer=Kemet, Tolerance_%=20%, Value1="0.08 ohm", Value2=10V, ValueDisplayed=10µF
C7 C8 C10 C28 C42 C43: library part CMP-0064931-4, "CAP, CERM, 0.1 uF, 10 V,+/- 10%, X7R, 0603", Cap_Case=0603, Manufacturer="Wurth Elektronik", Supplier Part Number 1=732-7939-1-ND, TempCo=X7R, Tolerance_%=10%, Value1=Unknown, Value2=10V, ValueDisplayed=0.1uF
C9: library part CMP-0090362-1, "0.1µF ±10% 10V Ceramic Capacitor X7R 0402 (1005 Metric)", Digikey Part Number=732-7513-1-ND, Manufacturer="Wurth Electronics", Mouser Part Number=710-885012205018, Operating Temperature Range="-55°C to +125°C", TempCo=15%, Temperature Characteristic=X7R, Tolerance_%=10%, ValueDisplayed=100000pF
C11 C12 C16 C17: library part CMP-0006215-2, "CAP, CERM, 10 pF, 50 V, +/- 5%, C0G/NP0, 0402", Cap_Case=0402, Manufacturer="Wurth Elektronik", Supplier Part Number 1=732-7469-1-ND, TempCo=C0G/NP0, Tolerance_%=5%, Value1=Unknown, Value2=50V, ValueDisplayed=10pF
C13 C22: library part CMP-0064924-2, "CAP, CERM, 1 uF, 10 V,+/- 20%, X5R, 0402", Cap_Case=0402, Manufacturer="Wurth Elektronik", Supplier Part Number 1=732-7489-1-ND, TempCo=X5R, Tolerance_%=20%, Value1=Unknown, Value2=10V, ValueDisplayed=1uF
C15 C20: library part CMP-0006227-2, "CAP, CERM, 0.01 uF, 16 V, +/- 10%, X7R, 0402", Cap_Case=0402, Manufacturer="Wurth Elektronik", Supplier Part Number 1=710-885012205031, TempCo=X7R, Tolerance_%=10%, Value1=Unknown, Value2=16V, ValueDisplayed=0.01uF
C18 C19: library part CMP-0006250-2, "CAP, CERM, 33 pF, 50 V, +/- 5%, C0G/NP0, 0402", Cap_Case=0402, Manufacturer=TDK, Supplier Part Number 1=445-1241-1-ND, TempCo=C0G/NP0, Tolerance_%=5%, Value1=Unknown, Value2=50V, ValueDisplayed=33pF
C21: library part CMP-0006222-2, "CAP, CERM, 2.2 uF, 10 V, +/- 20%, X5R, 0402", Cap_Case=0402, Manufacturer="Wurth Elektronik", Supplier Part Number 1=710-885012105013, TempCo=X5R, Tolerance_%=20%, Value1=Unknown, Value2=10V, ValueDisplayed=2.2uF
C23: library part CMP-0006269-2, "CAP, CERM, 4.7 uF, 10 V, +/- 20%, X5R, 0402", Cap_Case=0402, Manufacturer=TDK, Supplier Part Number 1=445-8023-1-ND, TempCo=X5R, Tolerance_%=20%, Value1=Unknown, Value2=10V, ValueDisplayed=4.7uF
C24: library part CMP-0006231-2, "CAP, CERM, 1000 pF, 50 V, +/- 10%, X7R, 0402", Cap_Case=0402, Manufacturer="Wurth Elektronik", Supplier Part Number 1=732-7556-1-ND, TempCo=X7R, Tolerance_%=10%, Value1=Unknown, Value2=50V, ValueDisplayed=1000pF
C25: library part CMP-0006562-2, "CAP, CERM, 0.1 uF, 10 V, +/- 10%, X5R, 0402", Cap_Case=0402, Manufacturer=MuRata, Supplier Part Number 1=490-1318-1-ND, TempCo=X5R, Tolerance_%=10%, Value1=Unknown, Value2=10V, ValueDisplayed=0.1uF
C26: library part CMP-0006833-4, "CAP, CERM, 1 uF, 25 V, +/- 10%, X7R, 0603", Cap_Case=0603, Manufacturer="Wurth Elektronik", Supplier Part Number 1=732-7994-1-ND, TempCo=X7R, Tolerance_%=10%, Value1=Unknown, Value2=25V, ValueDisplayed=1uF
C27: library part CMP-0007690-2, "CAP, CERM, 4.7 uF, 10 V, +/- 10%, X7R, 0805", Cap_Case=0805, Manufacturer="Wurth Elektronik", Supplier Part Number 1=710-885012207025, TempCo=X7R, Tolerance_%=10%, Value1=Unknown, Value2=10V, ValueDisplayed=4.7uF
C29: library part CMP-0011161-2, "CAP, AL, 47 uF, 50 V, +/- 20%, SMD", Cap_Case=6.3x7.7mm, Manufacturer="Wurth Elektronik", Supplier Part Number 1=732-8457-1-ND, Tolerance_%=20%, Value1=Unknown, Value2=50V, ValueDisplayed=47uF
C30: library part CMP-0007696-2, "CAP, CERM, 1 uF, 50 V, +/- 10%, X7R, 0805", Cap_Case=0805, Manufacturer="Wurth Elektronik", Supplier Part Number 1=710-885012207103, TempCo=X7R, Tolerance_%=10%, Value1=Unknown, Value2=50V, ValueDisplayed=1uF
C31 C33: library part CMP-0006837-4, "CAP, CERM, 0.1 uF, 50 V, +/- 10%, X7R, 0603", Cap_Case=0603, Manufacturer="Wurth Elektronik", TempCo=X7R, Tolerance_%=10%, Value1=Unknown, Value2=50V, ValueDisplayed=0.1uF
C32: library part CMP-0007330-5, "CAP, CERM, 4.7 uF, 10 V, +/- 20%, X5R, 0603", Cap_Case=0603, Manufacturer=MuRata, Supplier Part Number 1=490-10478-1-ND, TempCo=X5R, Tolerance_%=20%, Value1=Unknown, Value2=10V, ValueDisplayed=4.7uF
C34 C35: library part CMP-0006826-4, "CAP, CERM, 1000 pF, 16 V, +/- 10%, X7R, 0603", Cap_Case=0603, Manufacturer="Wurth Elektronik", Supplier Part Number 1=710-885012206034, TempCo=X7R, Tolerance_%=10%, Value1=Unknown, Value2=16V, ValueDisplayed=1000pF
C36 C37 C38 C39 C40 C41: library part CMP-0064933-4, "CAP, CERM, 1000 pF, 50 V,+/- 10%, X7R, 0603", Cap_Case=0603, Manufacturer="Wurth Elektronik", Supplier Part Number 1=732-8001-1-ND, TempCo=X7R, Tolerance_%=10%, Value1=Unknown, Value2=50V, ValueDisplayed=1000pF
C44: library part CMP-0860569-1, "CAP, CERM, 10 µF, 25 V,+/- 10%, X5R, 0603", Cap_Case=0603, Manufacturer=MuRata, TempCo=X5R, Tolerance_%=10%, Value2=25V, ValueDisplayed=10µF
C45: library part CMP-0006853-4, "CAP, CERM, 0.01 uF, 16 V, +/- 10%, X7R, 0603", Cap_Case=0603, Manufacturer=Kemet, Supplier Part Number 1=399-7841-1-ND, TempCo=X7R, Tolerance_%=10%, Value1=Unknown, Value2=16V, ValueDisplayed=0.01uF
C46: library part CMP-0007159-1, "CAP, CERM, 1000 pF, 25 V, +/- 5%, C0G/NP0, 0603", Alternate Manufacturer="Wurth Elektronik", Alternate PartNumber=885012206059, Cap_Case=0603, Manufacturer=MuRata, Supplier Part Number 1=GRM1885C1E102JA01D-ND, TempCo=C0G/NP0, Tolerance_%=5%, Value1=Unknown, Value2=25V, ValueDisplayed=1000pF
D1: library part CMP-0002947-3, "LED, Red, SMD", Color=Red, Manufacturer="Wurth Elektronik", Power_TotalModule=72mW, Value1=0.072W, Value2=2V
D2: "LED, Green, SMD", Color=green, Manufacturer="Wurth Elektronik", PartNumber=150060VS75000, Value1=W, Value2=2V
D4 D5 D7: library part CMP-0002960-2, "LED, Bright Green, SMD", Color="Bright Green", Manufacturer="Wurth Elektronik", Power_TotalModule=72mW, Supplier Part Number 1=732-4986-1-ND, Value1=0.072W, Value2=2V
D6: library part CMP-1426-00012-1, "SMD mono-color Chip LED, WL-SMCW, Yellow", Manufacturer="Wuerth Elektronik", PartNumber=150080YS75000
D8: library part CMP-0002951-3, "LED, Red, SMD", Color=Red, Manufacturer="Wurth Elektronik", Power_TotalModule=72mW, Value1=0.072W, Value2=1.9V
FID1 FID2 FID3: library part CMP-0077181-1, "Fiducial mark.  There is nothing to buy or mount.", Manufacturer=N/A
H1 H2 H3 H4: library part CMP-0003620-1, "Bumpon, Hemisphere, 0.44 X 0.20, Clear", Manufacturer=3M, Supplier Part Number 1=SJ5303-7-ND
J1: library part CMP-1502-03253-1, "Micro USB 2.0 Type B Receptacle WR-COM, Horizontal, SMT, with Pads and Pegs", Contact Resistance=30mOhm, Manufacturer="Wurth Elektronik", Operating Temperature=-40to105degC, Rated Current=1A, Working Voltage=30VAC
J2 J3: library part CMP-0086014-1, "Header, 2.54mm, 7x2, Gold, TH", Color=Black, Current_A=3A, Manufacturer="Wurth Elektronik", Voltage_V=250V
J4 J10 J11: library part CMP-1502-03256-1, "Series 101 - 5.00 mm Horizontal Entry Modular with Pressure Clamp WR-TBL, 2 pin", Manufacturer="Wurth Elektronik", Operating Temperature=-40to105degC
J5: library part CMP-0054796-2, "Header, 2.54 mm, 3x1, Gold, TH", Color=Black, Manufacturer="Wurth Elektronik", Supplier Part Number 1=732-5316-ND
J7: library part CMP-0054794-2, "Header, 2.54 mm, 2x1, Gold, TH", Color=Black, Manufacturer="Wurth Elektronik", Supplier Part Number 1=732-5315-ND
J9: library part CMP-0054623-2, "Header, 2.54mm, 10x2, Tin, TH", Color=Black, Current_A=3A, Manufacturer="Sullins Connector Solutions", Supplier Part Number 1=S2012E-10-ND
L1 L2: library part CMP-0003184-2, "Ferrite Bead, 140 ohm @ 100 MHz, 0.55 A, 0603", Manufacturer="Wurth Elektronik", Supplier Part Number 1=732-4663-1-ND, Value1="0.2 ohm", Value2=0.55A, ValueDisplayed="140 ohm"
LBL1: library part CMP-0003625-1, "Thermal Transfer Printable Labels, 0.650\" W x 0.200\" H - 10,000 per roll", Manufacturer=Brady, Supplier Part Number 1=97C5133
Logo1: library part CMP-0074838-1, "Texas Instrument Corporate Signature"
Logo2: library part CMP-0074844-1
Logo3: library part CMP-0074847-1, "FCC_disclaimer"
Logo4: library part CMP-0074769-1
P1.6 P1.7 P2.0 P2.1 P2.2 P2.3 P3.1 P3.4 P3.7: library part CMP-0003719-1, "Testpoint", Manufacturer="Texas Instruments"
R1: library part CMP-0026934-3, "RES, 470, 5%, 0.063 W, AEC-Q200 Grade 0, 0402", Manufacturer=Vishay-Dale, Power_W=63mW, Supplier Part Number 1=541-470JCT-ND, TempCo="200 ppm/C", Tolerance_%=5%, Value2=0.063W, Value_Code=470R, ValueDisplayed=470
R2: library part CMP-0026914-3, "RES, 390, 5%, 0.063 W, AEC-Q200 Grade 0, 0402", Manufacturer=Vishay-Dale, Power_W=63mW, Supplier Part Number 1=541-390JCT-ND, TempCo="200 ppm/C", Tolerance_%=5%, Value2=0.063W, Value_Code=390R, ValueDisplayed=390
R3: library part CMP-0026907-3, "RES, 33 k, 5%, 0.063 W, AEC-Q200 Grade 0, 0402", Manufacturer=Vishay-Dale, Power_W=63mW, Supplier Part Number 1=541-33KJCT-ND, TempCo="200 ppm/C", Tolerance_%=5%, Value2=0.063W, Value_Code=33k0, ValueDisplayed=33k
R4 R5: library part CMP-0026888-3, "RES, 27, 5%, 0.063 W, AEC-Q200 Grade 0, 0402", Manufacturer=Vishay-Dale, Power_W=63mW, Supplier Part Number 1=541-27JCT-ND, TempCo="200 ppm/C", Tolerance_%=5%, Value2=0.063W, Value_Code=27R0, ValueDisplayed=27
R6: library part CMP-0026859-2, "RES, 1.0 M, 5%, 0.063 W, AEC-Q200 Grade 0, 0402", Manufacturer=Vishay-Dale, Power_W=63mW, Supplier Part Number 1=541-1.0MJCT-ND, TempCo="200 ppm/C", Tolerance_%=5%, Value2=0.063W, Value_Code=1M00, ValueDisplayed=1.0M
R7: library part CMP-0026085-3, "RES, 1.40 k, 1%, 0.063 W, AEC-Q200 Grade 0, 0402", Manufacturer=Vishay-Dale, Power_W=63mW, Supplier Part Number 1=541-1.40KLCT-ND, TempCo="100 ppm/C", Tolerance_%=1%, Value2=0.063W, Value_Code=1k40, ValueDisplayed=1.40k
R8 R9 R10 R11: library part CMP-0025963-2, "RES, 10.0, 1%, 0.063 W, 0402", Manufacturer=Vishay-Dale, Power_W=63mW, Supplier Part Number 1=541-10.0LCT-ND, TempCo="100 ppm/C", Tolerance_%=1%, Value2=0.063W, Value_Code=10R0, ValueDisplayed=10.0
R12 R13: library part CMP-0026992-3, "RES, 0, 5%, 0.1 W, AEC-Q200 Grade 0, 0402", Manufacturer=Panasonic, Power_W=100mW, Supplier Part Number 1=P0.0JCT-ND, TempCo="600 ppm/C", Tolerance_%=5%, Value2=0.1W, Value_Code=0000, ValueDisplayed=0
R14: library part CMP-0026190-2, "RES, 240 k, 1%, 0.063 W, AEC-Q200 Grade 0, 0402", Manufacturer=Vishay-Dale, Power_W=63mW, Supplier Part Number 1=541-240KLCT-ND, TempCo="100 ppm/C", Tolerance_%=1%, Value2=0.063W, Value_Code=240k
R15: library part CMP-0026021-3, "RES, 150 k, 1%, 0.063 W, AEC-Q200 Grade 0, 0402", Manufacturer=Vishay-Dale, Power_W=63mW, Supplier Part Number 1=541-150KLCT-ND, TempCo="100 ppm/C", Tolerance_%=1%, Value2=0.063W, Value_Code=150k
R16 R17: library part CMP-0026728-1, "RES, 220 k, 1%, 0.0625 W, 0402", Manufacturer="Yageo America", Power_W=62.5mW, Supplier Part Number 1=311-220KLRCT-ND, TempCo="100 ppm/C", Tolerance_%=1%, Value2=0.0625W, Value_Code=220k
R18: library part CMP-0081856-1, "RES, 0, 0%, 0.2 W, AEC-Q200 Grade 0, 0402", Manufacturer=Vishay-Dale, Power_W=200mW, Supplier Part Number 1=541-0.0YBTR-ND, Tolerance_%=0%, Value2=0.2W, Value_Code=0
R19: library part CMP-0026935-3, "RES, 47 k, 5%, 0.063 W, AEC-Q200 Grade 0, 0402", Manufacturer=Vishay-Dale, Power_W=63mW, Supplier Part Number 1=541-47KJCT-ND, TempCo="200 ppm/C", Tolerance_%=5%, Value2=0.063W, Value_Code=47k0, ValueDisplayed=47k
R20: library part CMP-0025874-3, "RES, 0, 5%, 0.1 W, 0603", Manufacturer=Panasonic, Power_W=100mW, Supplier Part Number 1=P0.0GCT-ND, TempCo="600 ppm/C", Tolerance_%=5%, Value2=0.1W, Value_Code=0000, ValueDisplayed=0
R21 R22: library part CMP-0025697-4, "RES, 0, 5%, 0.1 W, AEC-Q200 Grade 0, 0603", Manufacturer=Vishay-Dale, Power_W=100mW, Supplier Part Number 1=541-0.0GCT-ND, TempCo="200 ppm/C", Tolerance_%=5%, Value2=0.1W, Value_Code=0000, ValueDisplayed=0
R23 R24: library part CMP-0015754-2, "RES, 0.2, 1%, 2 W, 2512", Manufacturer=Bourns, Power_W=2W, Supplier Part Number 1=CRM2512-FX-R200ELFCT-ND, TempCo="100 ppm/C", Tolerance_%=1%, Value_Code=R200, ValueDisplayed=0.2
R25: library part CMP-0025925-5, "RES, 47 k, 5%, 0.1 W, 0603", Manufacturer=Yageo, Power_W=100mW, Supplier Part Number 1=311-47KGRCT-ND, TempCo="100 ppm/C", Tolerance_%=5%, Value2=0.1W, Value_Code=47k0, ValueDisplayed=47k
R26 R29 R32 R35: library part CMP-0025785-4, "RES, 330, 5%, 0.1 W, AEC-Q200 Grade 0, 0603", Manufacturer=Vishay-Dale, Power_W=100mW, Supplier Part Number 1=541-330GCT-ND, TempCo="200 ppm/C", Tolerance_%=5%, Value2=0.1W, Value_Code=330R, ValueDisplayed=330
R27 R28: library part CMP-0022110-4, "RES, 1.02 k, 1%, 0.1 W, AEC-Q200 Grade 0, 0603", Manufacturer=Vishay-Dale, Power_W=100mW, Supplier Part Number 1=541-1.02KHCT-ND, TempCo="100 ppm/C", Tolerance_%=1%, Value2=0.1W, Value_Code=1k02, ValueDisplayed=1.02k
R30 R31: library part CMP-0025668-3, "RES, 9.09 k, 0.5%, 0.1 W, 0603", Manufacturer="Yageo America", Power_W=100mW, TempCo="50 ppm/C", Tolerance_%=0.5%, Value2=0.1W, Value_Code=9k09, ValueDisplayed=9.09k
R33: library part CMP-0022458-4, "RES, 4.99 k, 1%, 0.1 W, AEC-Q200 Grade 0, 0603", Manufacturer=Vishay-Dale, Power_W=100mW, Supplier Part Number 1=541-4.99KHCT-ND, TempCo="100 ppm/C", Tolerance_%=1%, Value2=0.1W, Value_Code=4k99, ValueDisplayed=4.99k
R34: library part CMP-0025701-4, "RES, 10 k, 5%, 0.1 W, AEC-Q200 Grade 0, 0603", Manufacturer=Vishay-Dale, Power_W=100mW, Supplier Part Number 1=541-10KGCT-ND, TempCo="200 ppm/C", Tolerance_%=5%, Value2=0.1W, Value_Code=10k0, ValueDisplayed=10k
R36: library part CMP-0025814-4, "RES, 47 k, 5%, 0.1 W, AEC-Q200 Grade 0, 0603", Manufacturer=Vishay-Dale, Power_W=100mW, Supplier Part Number 1=541-47KGCT-ND, TempCo="200 ppm/C", Tolerance_%=5%, Value2=0.1W, Value_Code=47k0, ValueDisplayed=47k
S1: library part CMP-1452-00025-1, "WS-TASV SMD Tact Switch 6X6 mm", Manufacturer="Wuerth Elektronik"
SH-J1 SH-J2 SH-J3 SH-J4 SH-J5 SH-J6 SH-J7 SH-J8 SH-J9 SH-J10 SH-J11 SH-J12 SH-J13 SH-J14 SH-J15 SH-J16 SH-J17 SH-J18 SH-J19 SH-J20: library part CMP-0003761-2, "Shunt, 2.54mm, Gold, Black", Manufacturer="Wurth Elektronik", Supplier Part Number 1=732-2678-ND
TP1 TP13 TP14 TP15 TP16: library part CMP-0055153-1, "Test Point, Compact, SMT", Manufacturer=Keystone, Supplier Part Number 1=36-5016TR-ND
TP7 TP8: "1mm Uninsulated Shorting Plug, 10.16mm spacing, TH", Manufacturer=Harwin, PartNumber=D3082-05, Supplier Part Number 1=952-1873-ND
TP17 TP18 TP19 TP20 TP21 TP22 TP23 TP24 TP25 TP26: library part CMP-0055139-2, "Test Point, Miniature, White, TH", Color=White, Manufacturer="Keystone Electronics", Supplier Part Number 1=36-5002-ND
U1: "16-Bit Ultra-Low-Power Microcontroller, 128KB Flash, 8KB RAM, USB, 12Bit ADC, 2 USCIs, 32Bit HW MPY, RGC0064B (VQFN-64)", Alternate Manufacturer="Texas Instruments", Alternate PartNumber=MSP430F5528IRGCR, Frequency(MHz)=25, Operating Temperature Range="-40 to 85 C", PartNumber=MSP430F5528IRGCT, Rating=Catalog, Temp Sensor=Yes
U2: library part CMP-0043099-3, "Low-Capacitance 2-Channel +/-15kV ESD Protection Array for High-Speed Data Interfaces, DRY0006A (USON-6)", Breakdown Voltage(Min)(V)=11, IO Capacitance(Typ)(pF)=1.5, IO Leakage Current(nA)=1, Manufacturer="Texas Instruments", Operating Temperature Range="-40 to 85 C", PartNumber=q, Rating=Catalog
U3: library part CMP-0036330-5, "Single Output High PSRR LDO, 500 mA, Fixed 3.3 V Output, 2.7 to 6.5 V Input, with Low IQ, 6-pin SON (DRV), -40 to 125 degC, Green (RoHS & no Sb/Br)", Manufacturer="Texas Instruments"
U4: library part CMP-0073793-1, "150-mA, 30-V, Ultra-Low IQ, Wide Input Low-Dropout Regulator with Reverse Current Protection, DBV0005A (SOT-23-5)", Alternate Manufacturer="Texas Instruments", Alternate PartNumber=TPS70933DBVT
U5: library part CMP-0039449-2, "MSP430G2x53, MSP430G2x13 Mixed Signal Microcontroller, PW0028A (TSSOP-28)", Alternate Manufacturer="Texas Instruments", Alternate PartNumber=MSP430G2553IPW28, Frequency(MHz)=16, Temp Sensor=Yes
U6: library part CMP-0094668-1, "Dual H-Bridge Motor Driver with Current Regulation", Manufacturer="Texas Instruments", Max Supply Voltage=11V, Min Supply Voltage=1.65V, Operating Temperature Range="-40°C to +150°C", Switching Frequency=100kHz
U7 U8: library part CMP-0073548-2, "1-MHz, Low-Power Operational Amplifier for Cost-Sensitive Systems, DCK0005A (SOT-SC70-5)", Alternate Manufacturer="Texas Instruments", Alternate PartNumber=TLV6001IDCKT
Y1: library part CMP-0085483-1, "Oscillator, 4 MHz, 700 ppm, 39 pF, SMD", Frequency_Fixed=4MHz, Frequency Tolerance="700 ppm", Load Capacitance="39 pF", Manufacturer=MuRata
ZZ1: library part CMP-0003616-3
ZZ2: library part CMP-0077236-1
ZZ3: library part CMP-0077237-1
ZZ4: library part CMP-0077238-1

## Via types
v1: diameter 0.635/0.635/0.635/0.635 (per signal layer), hole 0.305, Top Layer to Bottom Layer, tented both sides, 231 vias

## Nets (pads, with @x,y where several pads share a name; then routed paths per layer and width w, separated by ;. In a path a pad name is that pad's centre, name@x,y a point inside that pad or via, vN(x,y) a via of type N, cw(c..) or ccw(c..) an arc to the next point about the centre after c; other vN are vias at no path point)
AIN1: J9.2 TP17.1 U6.16 | length 48
  Top Layer w0.254: J9.2@34.452,56.219 35.35,56.219 TP17.1@38.725,59.594 ; U6.16@55.224,33.299 55.429,33.094 v1(55.429,31.5)
  Bottom Layer w0.254: TP17.1@38.725,59.594 36.631,57.5 36.631,45.25 38.05,43.831 39.281,43.831 40.068,43.045 40.068,41.862 50.43,31.5 v1(55.429,31.5)
AIN1_MCU: J9.1 U5.20 | length 15.1
  Top Layer w0.254: U5.20@18.475,53.7 18.475,54.685 19.54,55.75 31.444,55.75 J9.1@31.912,56.219
AIN2: J9.4 TP18.1 U6.15 | length 43.5
  Top Layer w0.254: J9.4@34.452,53.679 36.231,53.679 TP18.1@38.725,56.173 ; v1(54.579,32.225) 54.579,32.419 53.893,33.105 53.893,33.628 54.214,33.949 U6.15@55.224,33.949
  Bottom Layer w0.254: TP18.1@38.725,56.173 37.085,54.533 37.085,45.438 38.238,44.285 39.469,44.285 40.522,43.233 40.522,42.05 50.347,32.225 v1(54.579,32.225)
AIN2_MCU: J9.3 U5.19 | length 14.7
  Top Layer w0.254: U5.19@19.125,53.7 19.125,54.693 19.682,55.25 30.341,55.25 J9.3@31.912,53.679
AISEN: C34.1 J7.1 R23.2 U6.3 U7.1 | length 14.6
  Bottom Layer w0.254: U7.1@66.125,26.456 66.125,28.025 67.25,29.15 C34.1@68.75,29.15 68.75,33.088 69.952,34.29 74.117,34.29 J7.1@74.219,34.392
  other v1: 64.683,30.785 65.735,30.785 66.751,30.785 67.767,30.785 68.75,30.785 64.683,31.852 65.735,31.852 66.751,31.852 67.767,31.852 68.75,31.852 68.75,32.766 72.847,33.628 75.895,33.628 72.847,34.9 75.895,34.9
AOUT1: C36.1 C40.1 J10.1 TP13.1 U6.2 | length 6
  Top Layer w0.381: TP13.1@79.4,16.764 TP13.1@79.4,18.326
  Bottom Layer w0.381: C36.1@76.048,24.294 76.048,22.646 C40.1@76.138,22.555 78.762,22.555 J10.1@78.791,22.584
AOUT2: C36.2 C37.1 J10.2 TP14.1 U6.4 | length 6
  Top Layer w0.381: TP14.1@79.4,31.767 TP14.1@79.4,33.19
  Bottom Layer w0.381: C36.2@76.048,25.694 76.048,27.494 C37.1@76.138,27.584 J10.2@78.791,27.584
